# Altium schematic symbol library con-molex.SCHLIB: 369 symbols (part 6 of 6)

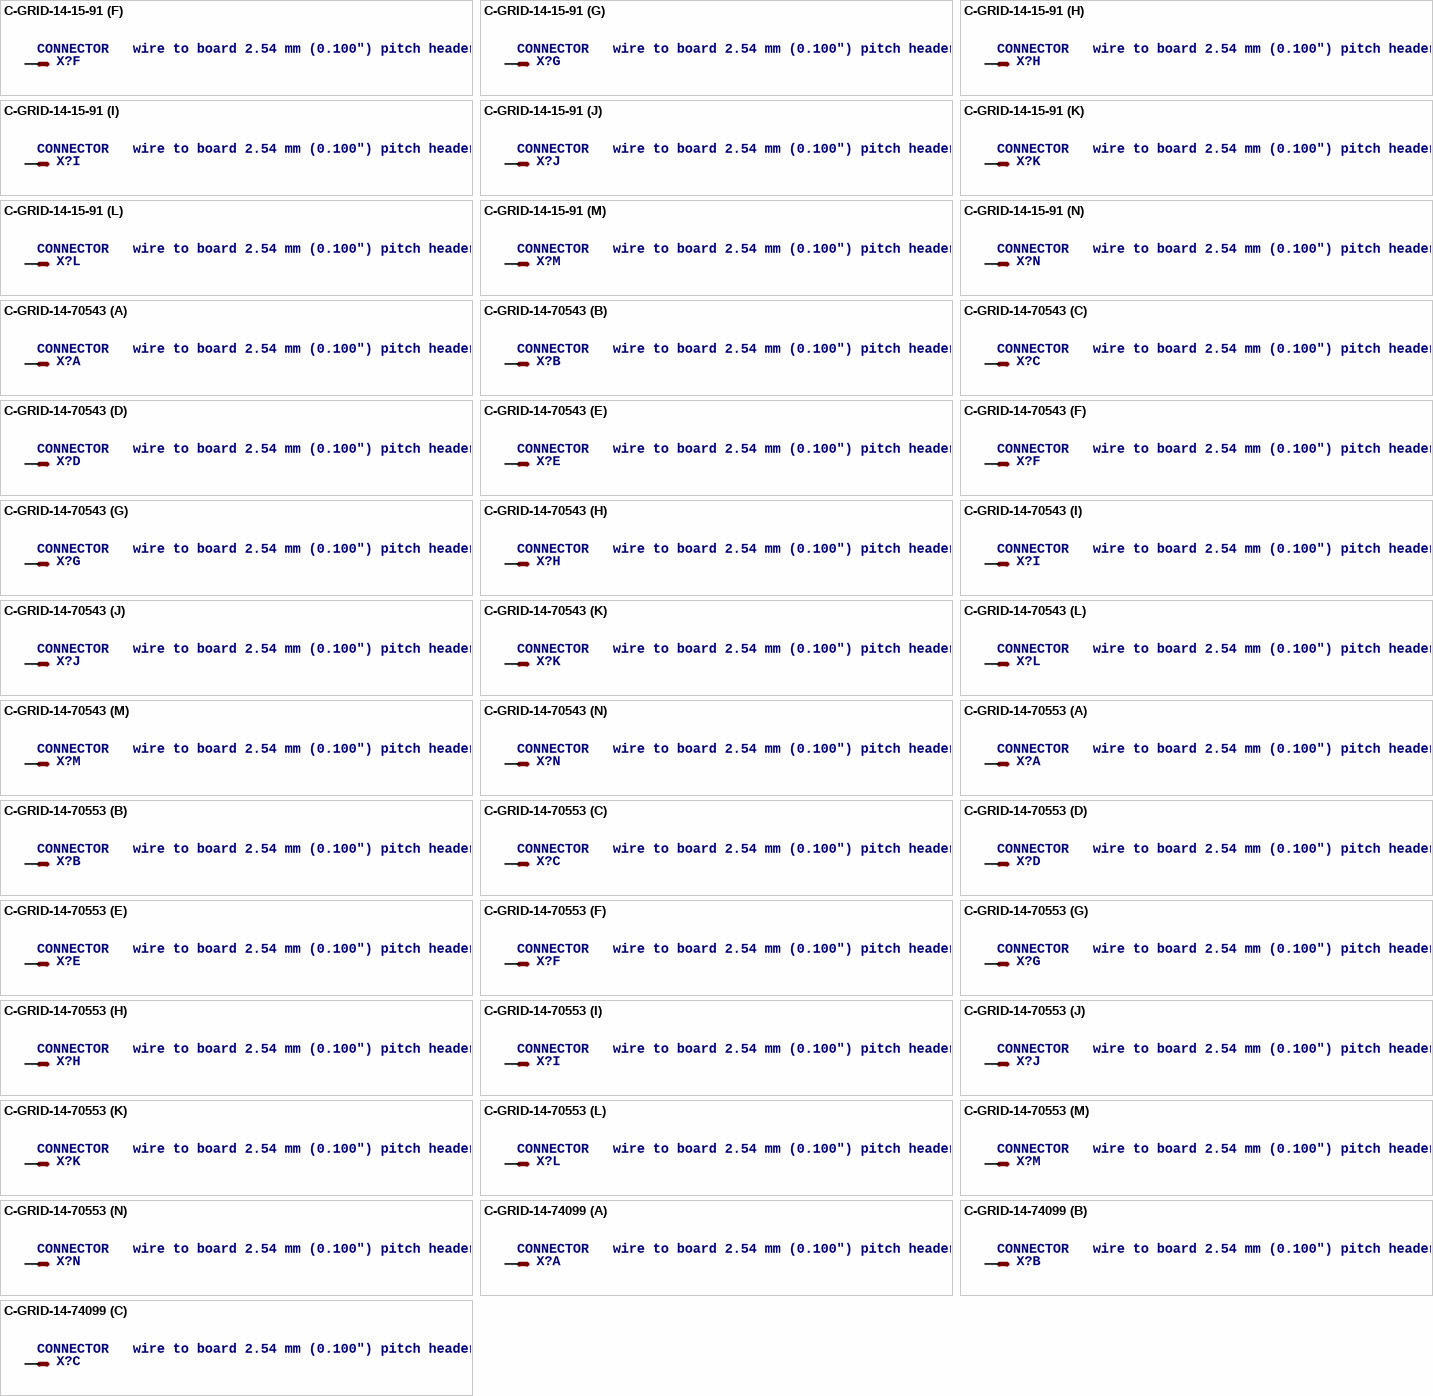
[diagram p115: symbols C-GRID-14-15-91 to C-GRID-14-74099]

## C-GRID-14-15-91
designator X?, comment CONNECTOR   wire to board 2.54 mm (0.100") pitch header
footprint 15-91-14
part A pins: 1 S
part B pins: 2 S
part C pins: 3 S
part D pins: 4 S
part E pins: 5 S
part F pins: 6 S
part G pins: 7 S
part H pins: 8 S
part I pins: 9 S
part J pins: 10 S
part K pins: 11 S
part L pins: 12 S
part M pins: 13 S
part N pins: 14 S

## C-GRID-14-70543
designator X?, comment CONNECTOR   wire to board 2.54 mm (0.100") pitch header
footprint 70543-14
part A pins: 1 S
part B pins: 2 S
part C pins: 3 S
part D pins: 4 S
part E pins: 5 S
part F pins: 6 S
part G pins: 7 S
part H pins: 8 S
part I pins: 9 S
part J pins: 10 S
part K pins: 11 S
part L pins: 12 S
part M pins: 13 S
part N pins: 14 S

## C-GRID-14-70553
designator X?, comment CONNECTOR   wire to board 2.54 mm (0.100") pitch header
footprint 70553-14
part A pins: 1 S
part B pins: 2 S
part C pins: 3 S
part D pins: 4 S
part E pins: 5 S
part F pins: 6 S
part G pins: 7 S
part H pins: 8 S
part I pins: 9 S
part J pins: 10 S
part K pins: 11 S
part L pins: 12 S
part M pins: 13 S
part N pins: 14 S

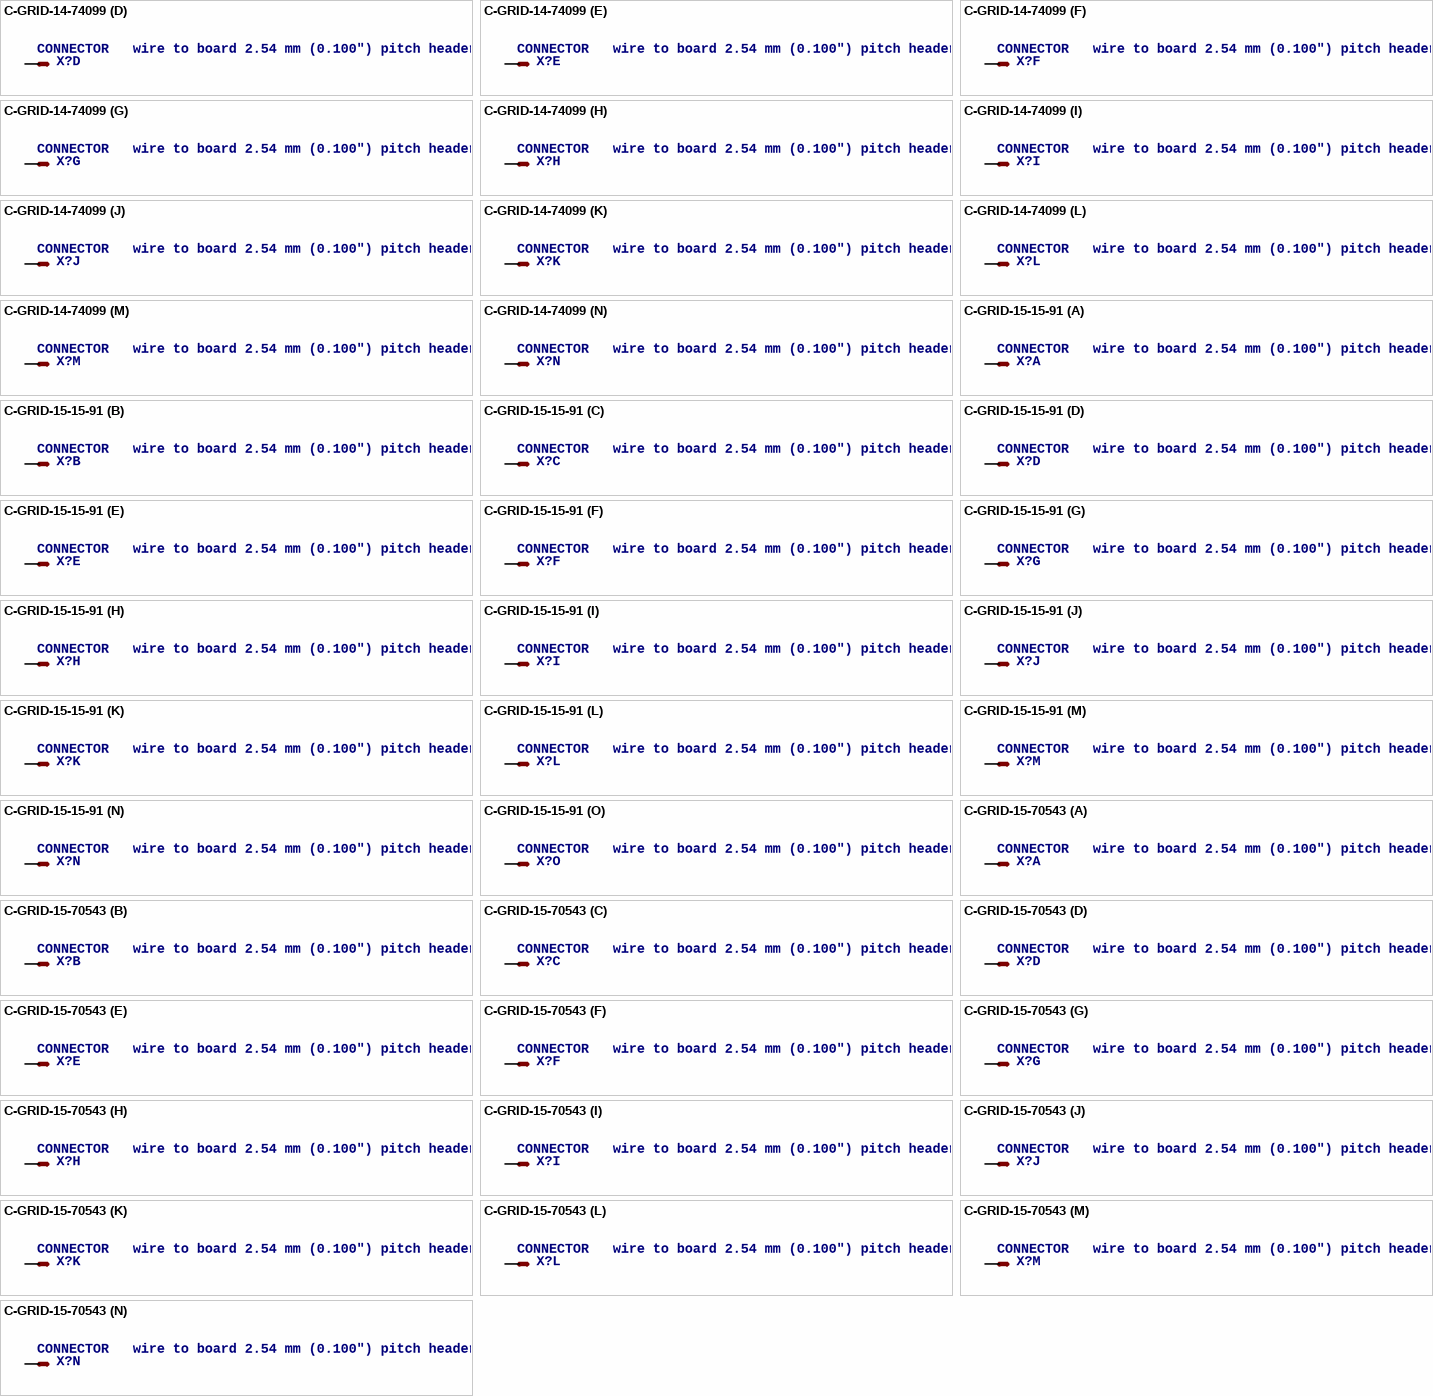
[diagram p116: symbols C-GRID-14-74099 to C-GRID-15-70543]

## C-GRID-14-74099
designator X?, comment CONNECTOR   wire to board 2.54 mm (0.100") pitch header
footprint 74099-14
part A pins: 1 S
part B pins: 2 S
part C pins: 3 S
part D pins: 4 S
part E pins: 5 S
part F pins: 6 S
part G pins: 7 S
part H pins: 8 S
part I pins: 9 S
part J pins: 10 S
part K pins: 11 S
part L pins: 12 S
part M pins: 13 S
part N pins: 14 S

## C-GRID-15-15-91
designator X?, comment CONNECTOR   wire to board 2.54 mm (0.100") pitch header
footprint 15-91-15
part A pins: 1 S
part B pins: 2 S
part C pins: 3 S
part D pins: 4 S
part E pins: 5 S
part F pins: 6 S
part G pins: 7 S
part H pins: 8 S
part I pins: 9 S
part J pins: 10 S
part K pins: 11 S
part L pins: 12 S
part M pins: 13 S
part N pins: 14 S
part O pins: 15 S

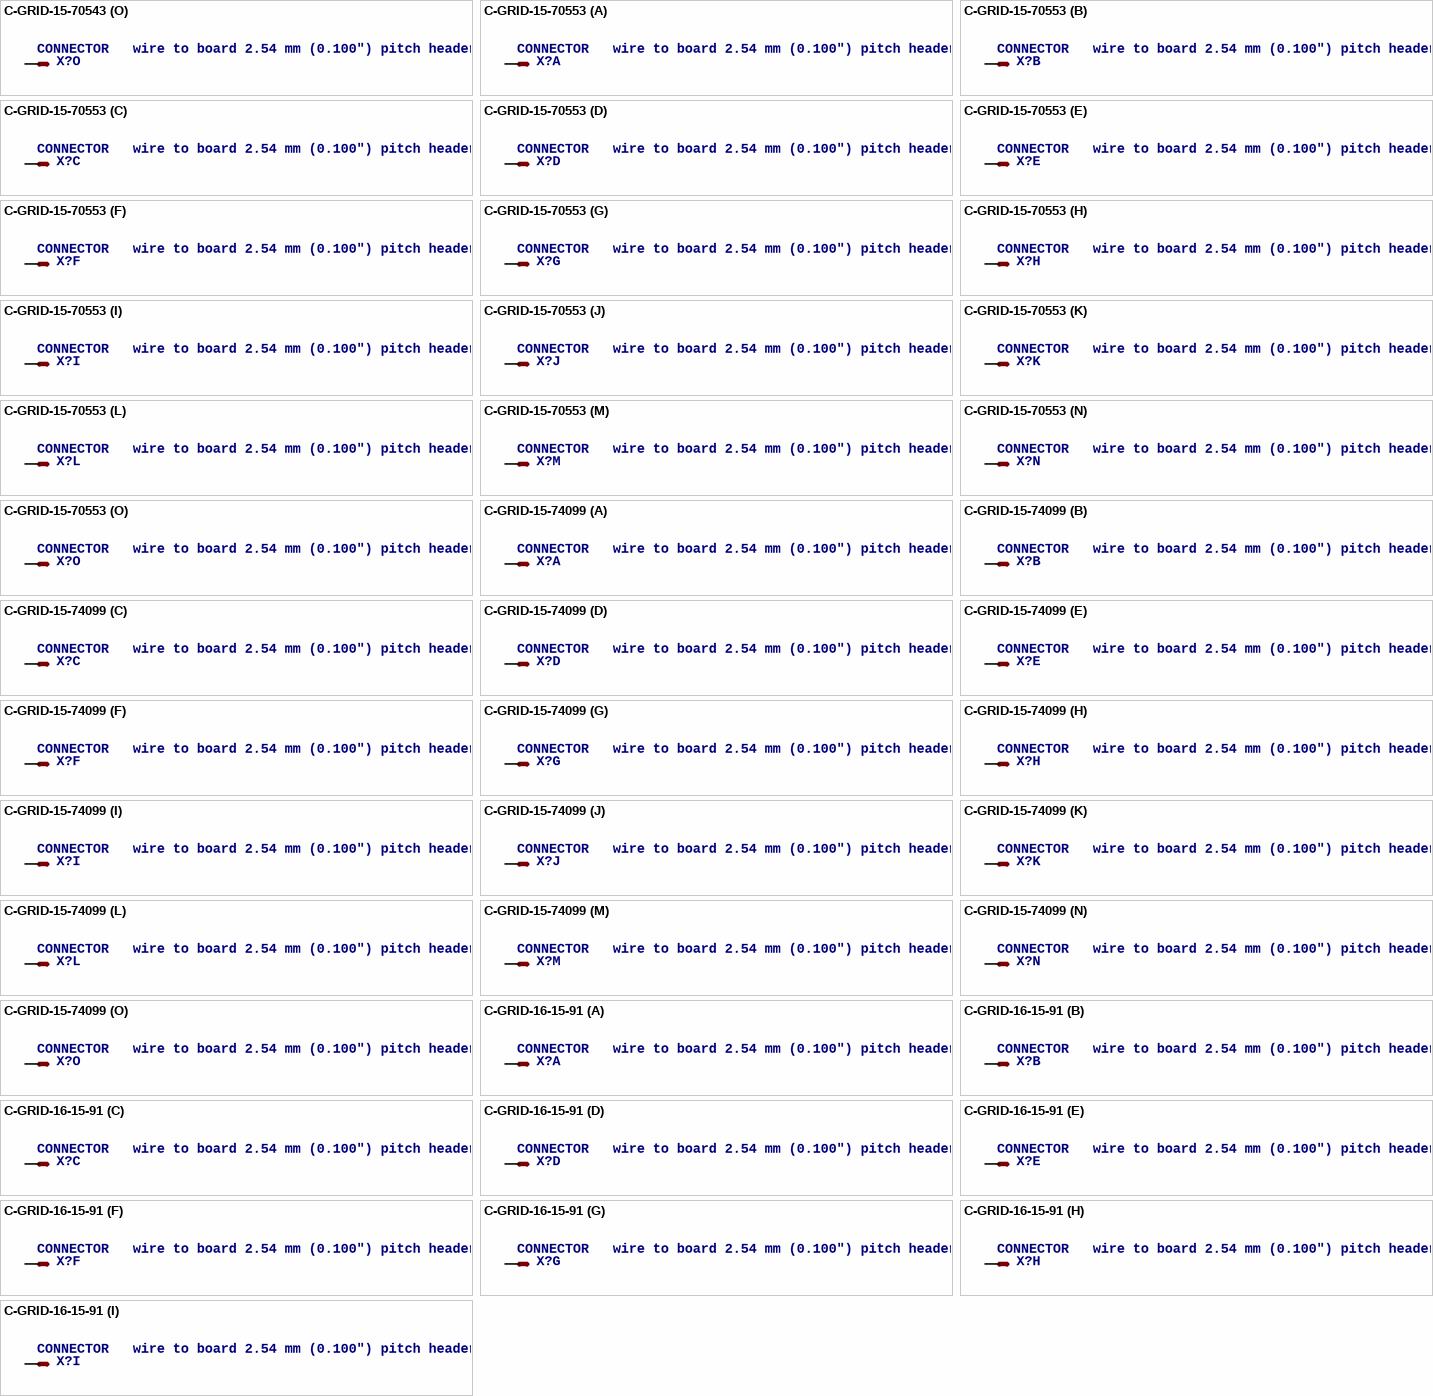
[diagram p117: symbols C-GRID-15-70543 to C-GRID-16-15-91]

## C-GRID-15-70543
designator X?, comment CONNECTOR   wire to board 2.54 mm (0.100") pitch header
footprint 70543-15
part A pins: 1 S
part B pins: 2 S
part C pins: 3 S
part D pins: 4 S
part E pins: 5 S
part F pins: 6 S
part G pins: 7 S
part H pins: 8 S
part I pins: 9 S
part J pins: 10 S
part K pins: 11 S
part L pins: 12 S
part M pins: 13 S
part N pins: 14 S
part O pins: 15 S

## C-GRID-15-70553
designator X?, comment CONNECTOR   wire to board 2.54 mm (0.100") pitch header
footprint 70553-15
part A pins: 1 S
part B pins: 2 S
part C pins: 3 S
part D pins: 4 S
part E pins: 5 S
part F pins: 6 S
part G pins: 7 S
part H pins: 8 S
part I pins: 9 S
part J pins: 10 S
part K pins: 11 S
part L pins: 12 S
part M pins: 13 S
part N pins: 14 S
part O pins: 15 S

## C-GRID-15-74099
designator X?, comment CONNECTOR   wire to board 2.54 mm (0.100") pitch header
footprint 74099-15
part A pins: 1 S
part B pins: 2 S
part C pins: 3 S
part D pins: 4 S
part E pins: 5 S
part F pins: 6 S
part G pins: 7 S
part H pins: 8 S
part I pins: 9 S
part J pins: 10 S
part K pins: 11 S
part L pins: 12 S
part M pins: 13 S
part N pins: 14 S
part O pins: 15 S

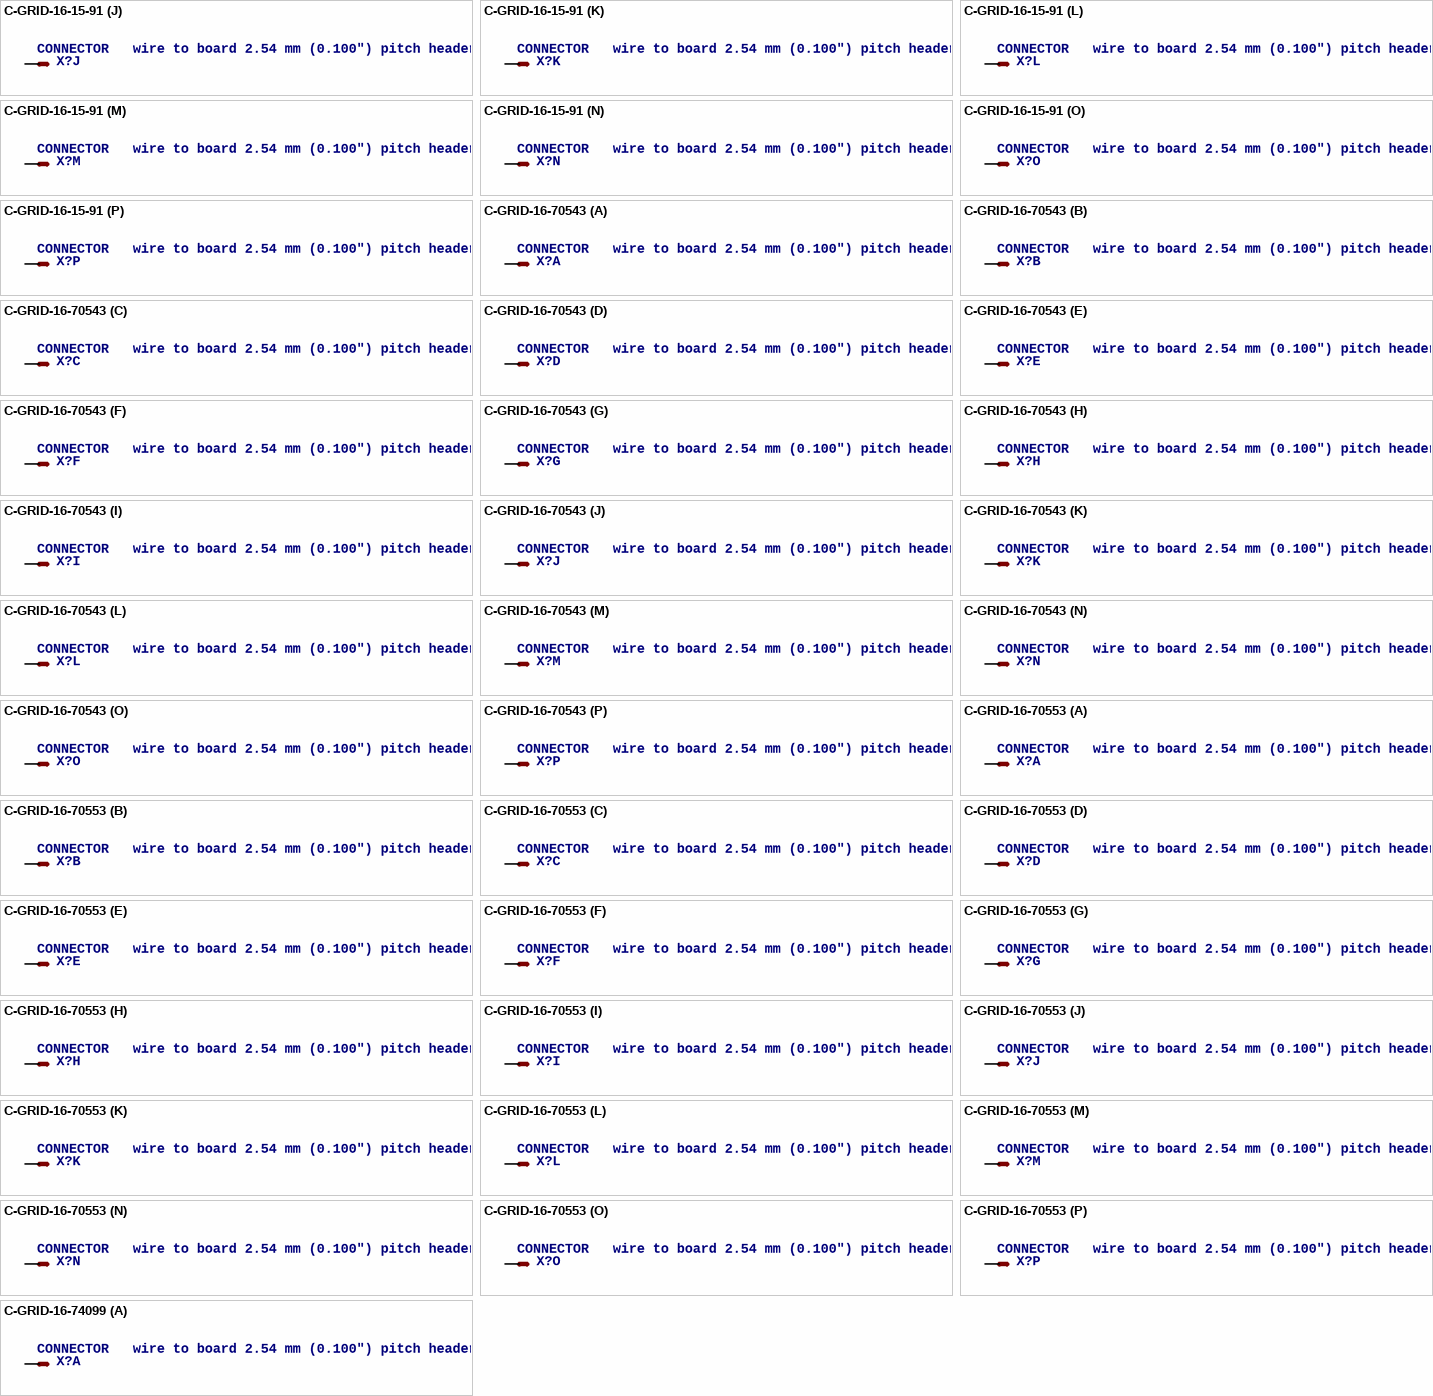
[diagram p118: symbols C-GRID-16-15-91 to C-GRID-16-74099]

## C-GRID-16-15-91
designator X?, comment CONNECTOR   wire to board 2.54 mm (0.100") pitch header
footprint 15-91-16
part A pins: 1 S
part B pins: 2 S
part C pins: 3 S
part D pins: 4 S
part E pins: 5 S
part F pins: 6 S
part G pins: 7 S
part H pins: 8 S
part I pins: 9 S
part J pins: 10 S
part K pins: 11 S
part L pins: 12 S
part M pins: 13 S
part N pins: 14 S
part O pins: 15 S
part P pins: 16 S

## C-GRID-16-70543
designator X?, comment CONNECTOR   wire to board 2.54 mm (0.100") pitch header
footprint 70543-16
part A pins: 1 S
part B pins: 2 S
part C pins: 3 S
part D pins: 4 S
part E pins: 5 S
part F pins: 6 S
part G pins: 7 S
part H pins: 8 S
part I pins: 9 S
part J pins: 10 S
part K pins: 11 S
part L pins: 12 S
part M pins: 13 S
part N pins: 14 S
part O pins: 15 S
part P pins: 16 S

## C-GRID-16-70553
designator X?, comment CONNECTOR   wire to board 2.54 mm (0.100") pitch header
footprint 70553-16
part A pins: 1 S
part B pins: 2 S
part C pins: 3 S
part D pins: 4 S
part E pins: 5 S
part F pins: 6 S
part G pins: 7 S
part H pins: 8 S
part I pins: 9 S
part J pins: 10 S
part K pins: 11 S
part L pins: 12 S
part M pins: 13 S
part N pins: 14 S
part O pins: 15 S
part P pins: 16 S

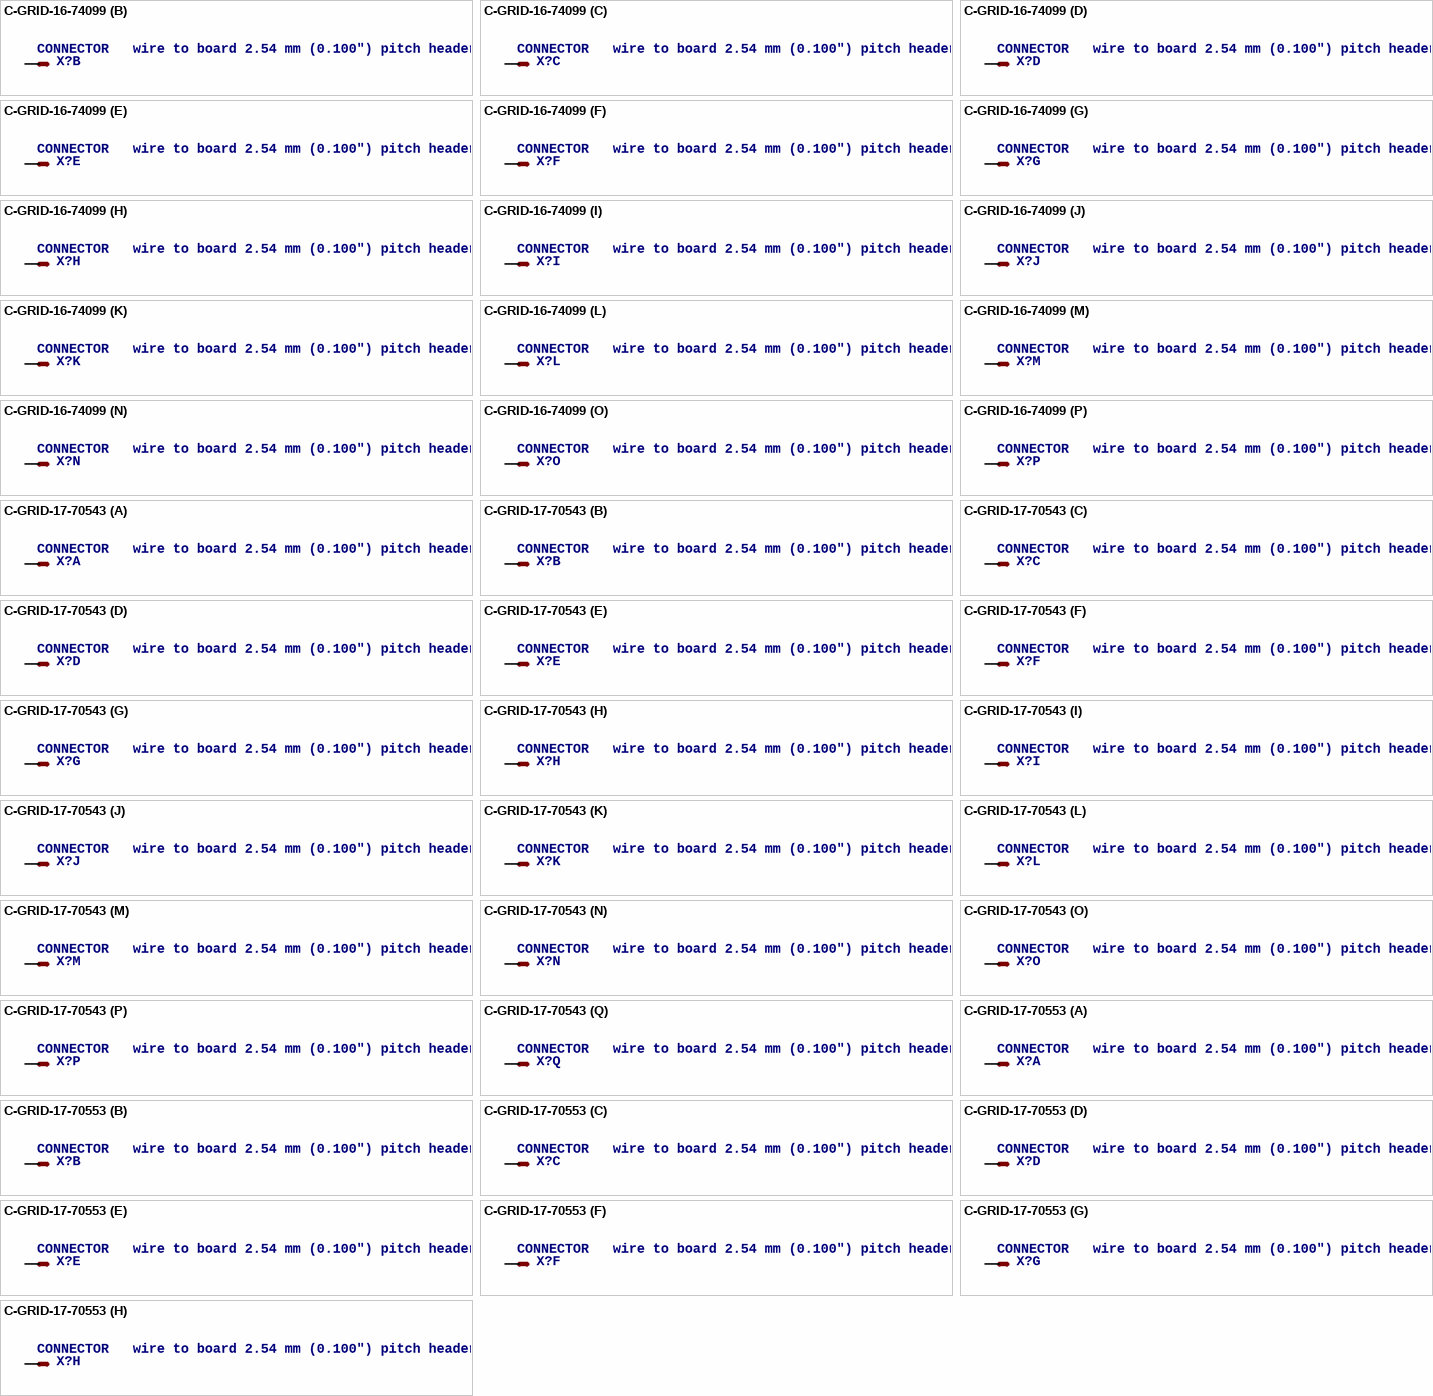
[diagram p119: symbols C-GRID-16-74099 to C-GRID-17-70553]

## C-GRID-16-74099
designator X?, comment CONNECTOR   wire to board 2.54 mm (0.100") pitch header
footprint 74099-16
part A pins: 1 S
part B pins: 2 S
part C pins: 3 S
part D pins: 4 S
part E pins: 5 S
part F pins: 6 S
part G pins: 7 S
part H pins: 8 S
part I pins: 9 S
part J pins: 10 S
part K pins: 11 S
part L pins: 12 S
part M pins: 13 S
part N pins: 14 S
part O pins: 15 S
part P pins: 16 S

## C-GRID-17-70543
designator X?, comment CONNECTOR   wire to board 2.54 mm (0.100") pitch header
footprint 70543-17
part A pins: 1 S
part B pins: 2 S
part C pins: 3 S
part D pins: 4 S
part E pins: 5 S
part F pins: 6 S
part G pins: 7 S
part H pins: 8 S
part I pins: 9 S
part J pins: 10 S
part K pins: 11 S
part L pins: 12 S
part M pins: 13 S
part N pins: 14 S
part O pins: 15 S
part P pins: 16 S
part Q pins: 17 S

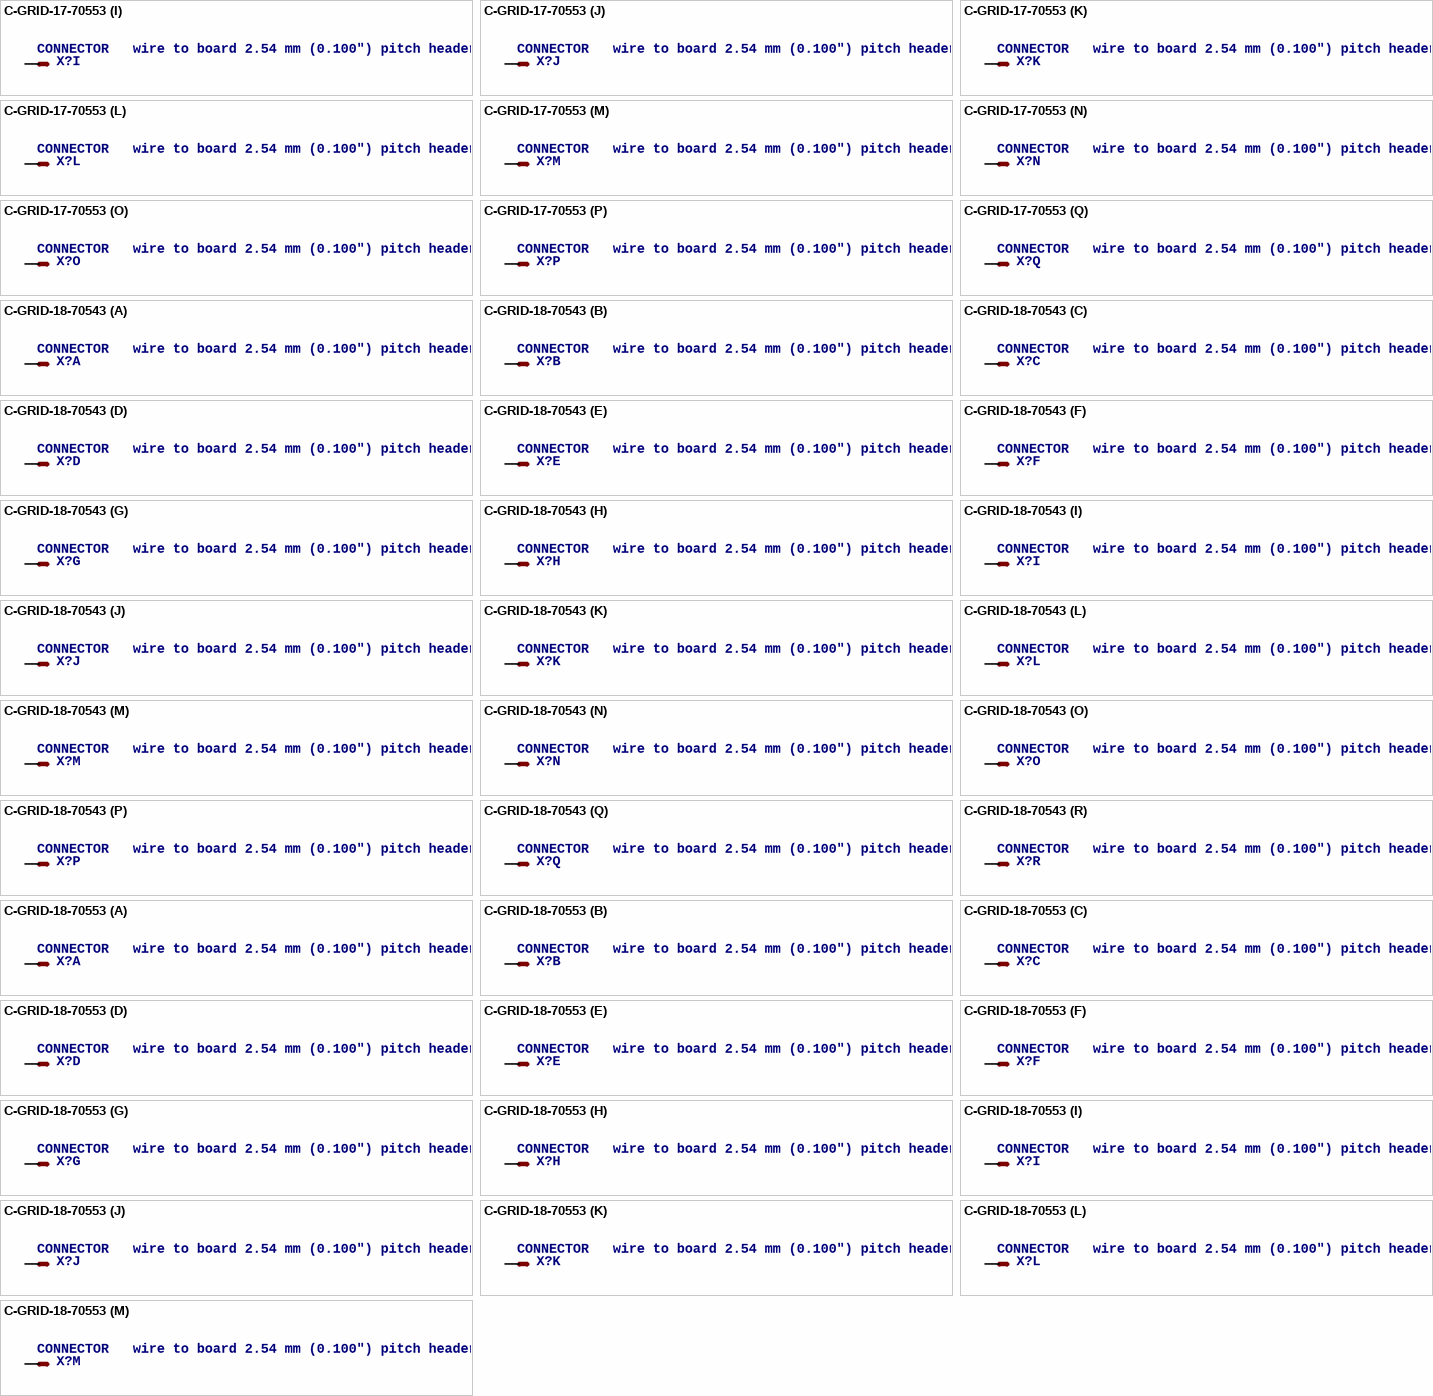
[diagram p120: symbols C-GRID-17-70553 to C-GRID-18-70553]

## C-GRID-17-70553
designator X?, comment CONNECTOR   wire to board 2.54 mm (0.100") pitch header
footprint 70553-17
part A pins: 1 S
part B pins: 2 S
part C pins: 3 S
part D pins: 4 S
part E pins: 5 S
part F pins: 6 S
part G pins: 7 S
part H pins: 8 S
part I pins: 9 S
part J pins: 10 S
part K pins: 11 S
part L pins: 12 S
part M pins: 13 S
part N pins: 14 S
part O pins: 15 S
part P pins: 16 S
part Q pins: 17 S

## C-GRID-18-70543
designator X?, comment CONNECTOR   wire to board 2.54 mm (0.100") pitch header
footprint 70543-18
part A pins: 1 S
part B pins: 2 S
part C pins: 3 S
part D pins: 4 S
part E pins: 5 S
part F pins: 6 S
part G pins: 7 S
part H pins: 8 S
part I pins: 9 S
part J pins: 10 S
part K pins: 11 S
part L pins: 12 S
part M pins: 13 S
part N pins: 14 S
part O pins: 15 S
part P pins: 16 S
part Q pins: 17 S
part R pins: 18 S

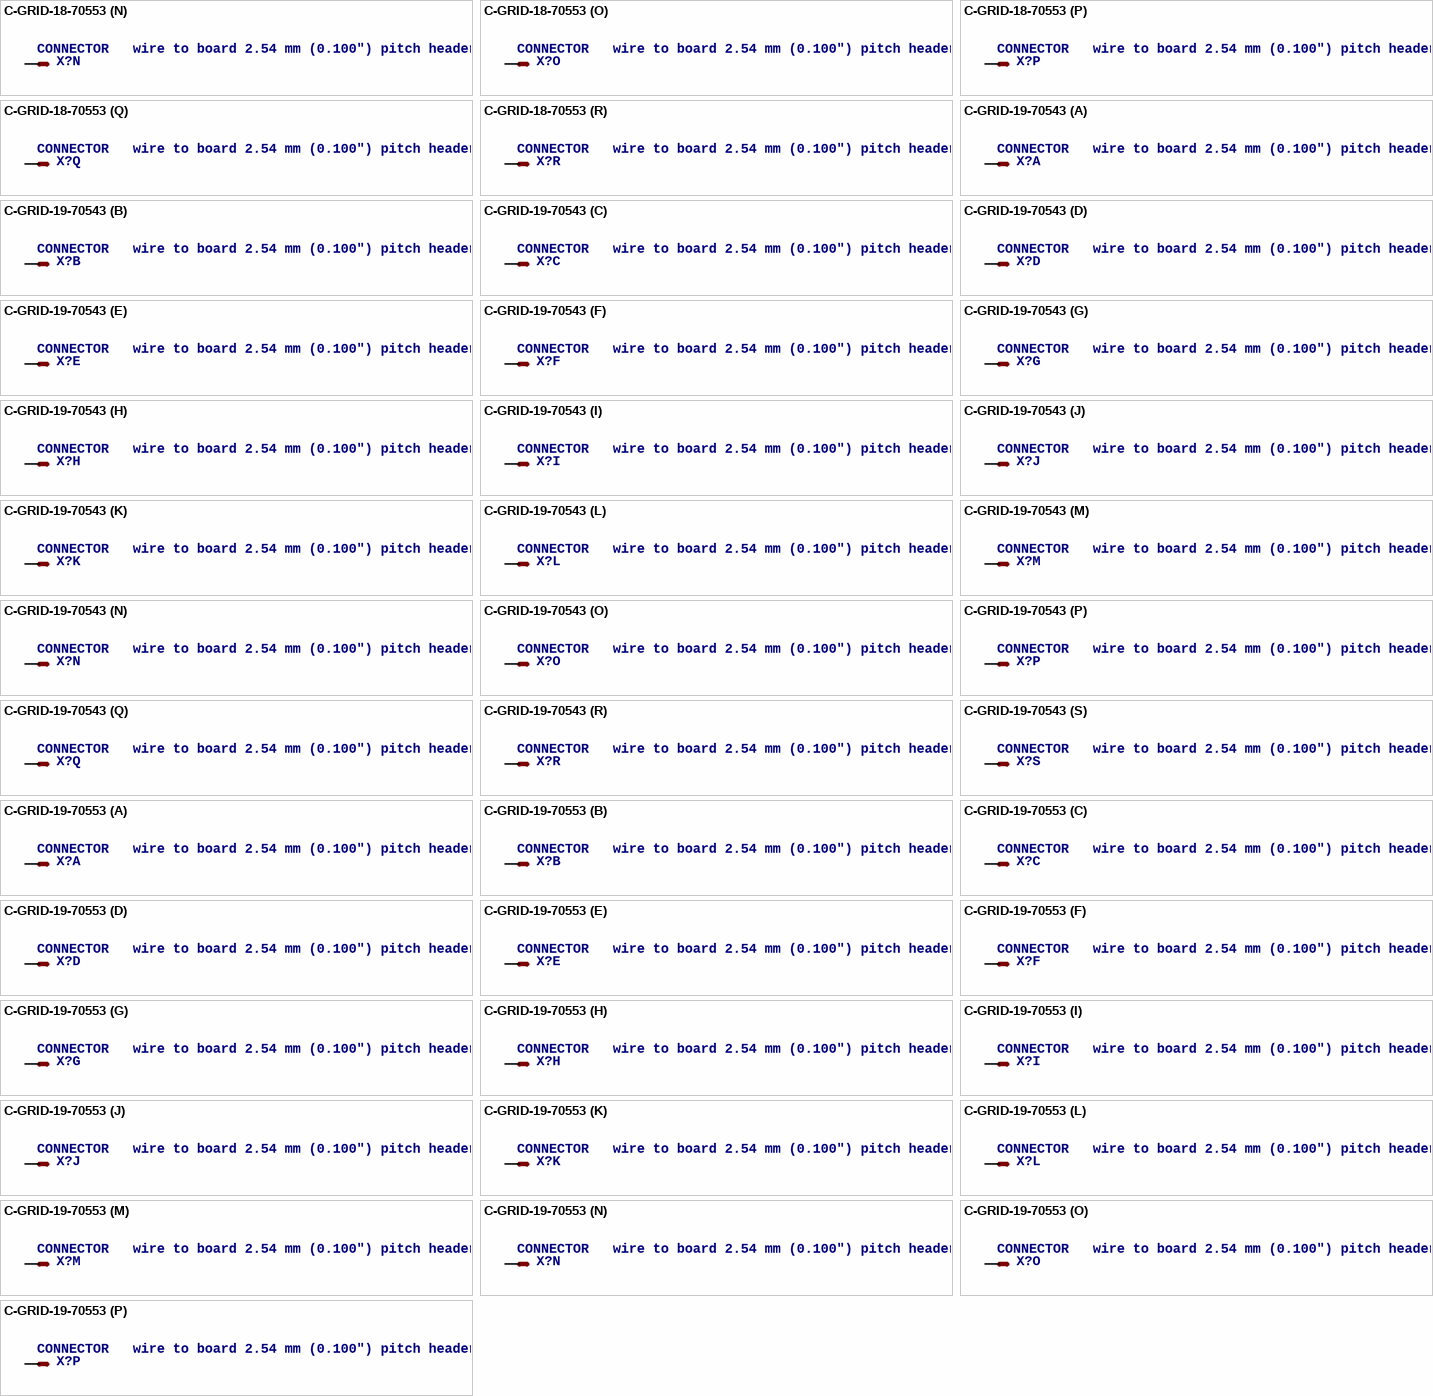
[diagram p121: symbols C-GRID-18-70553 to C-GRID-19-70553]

## C-GRID-18-70553
designator X?, comment CONNECTOR   wire to board 2.54 mm (0.100") pitch header
footprint 70553-18
part A pins: 1 S
part B pins: 2 S
part C pins: 3 S
part D pins: 4 S
part E pins: 5 S
part F pins: 6 S
part G pins: 7 S
part H pins: 8 S
part I pins: 9 S
part J pins: 10 S
part K pins: 11 S
part L pins: 12 S
part M pins: 13 S
part N pins: 14 S
part O pins: 15 S
part P pins: 16 S
part Q pins: 17 S
part R pins: 18 S

## C-GRID-19-70543
designator X?, comment CONNECTOR   wire to board 2.54 mm (0.100") pitch header
footprint 70543-19
part A pins: 1 S
part B pins: 2 S
part C pins: 3 S
part D pins: 4 S
part E pins: 5 S
part F pins: 6 S
part G pins: 7 S
part H pins: 8 S
part I pins: 9 S
part J pins: 10 S
part K pins: 11 S
part L pins: 12 S
part M pins: 13 S
part N pins: 14 S
part O pins: 15 S
part P pins: 16 S
part Q pins: 17 S
part R pins: 18 S
part S pins: 19 S

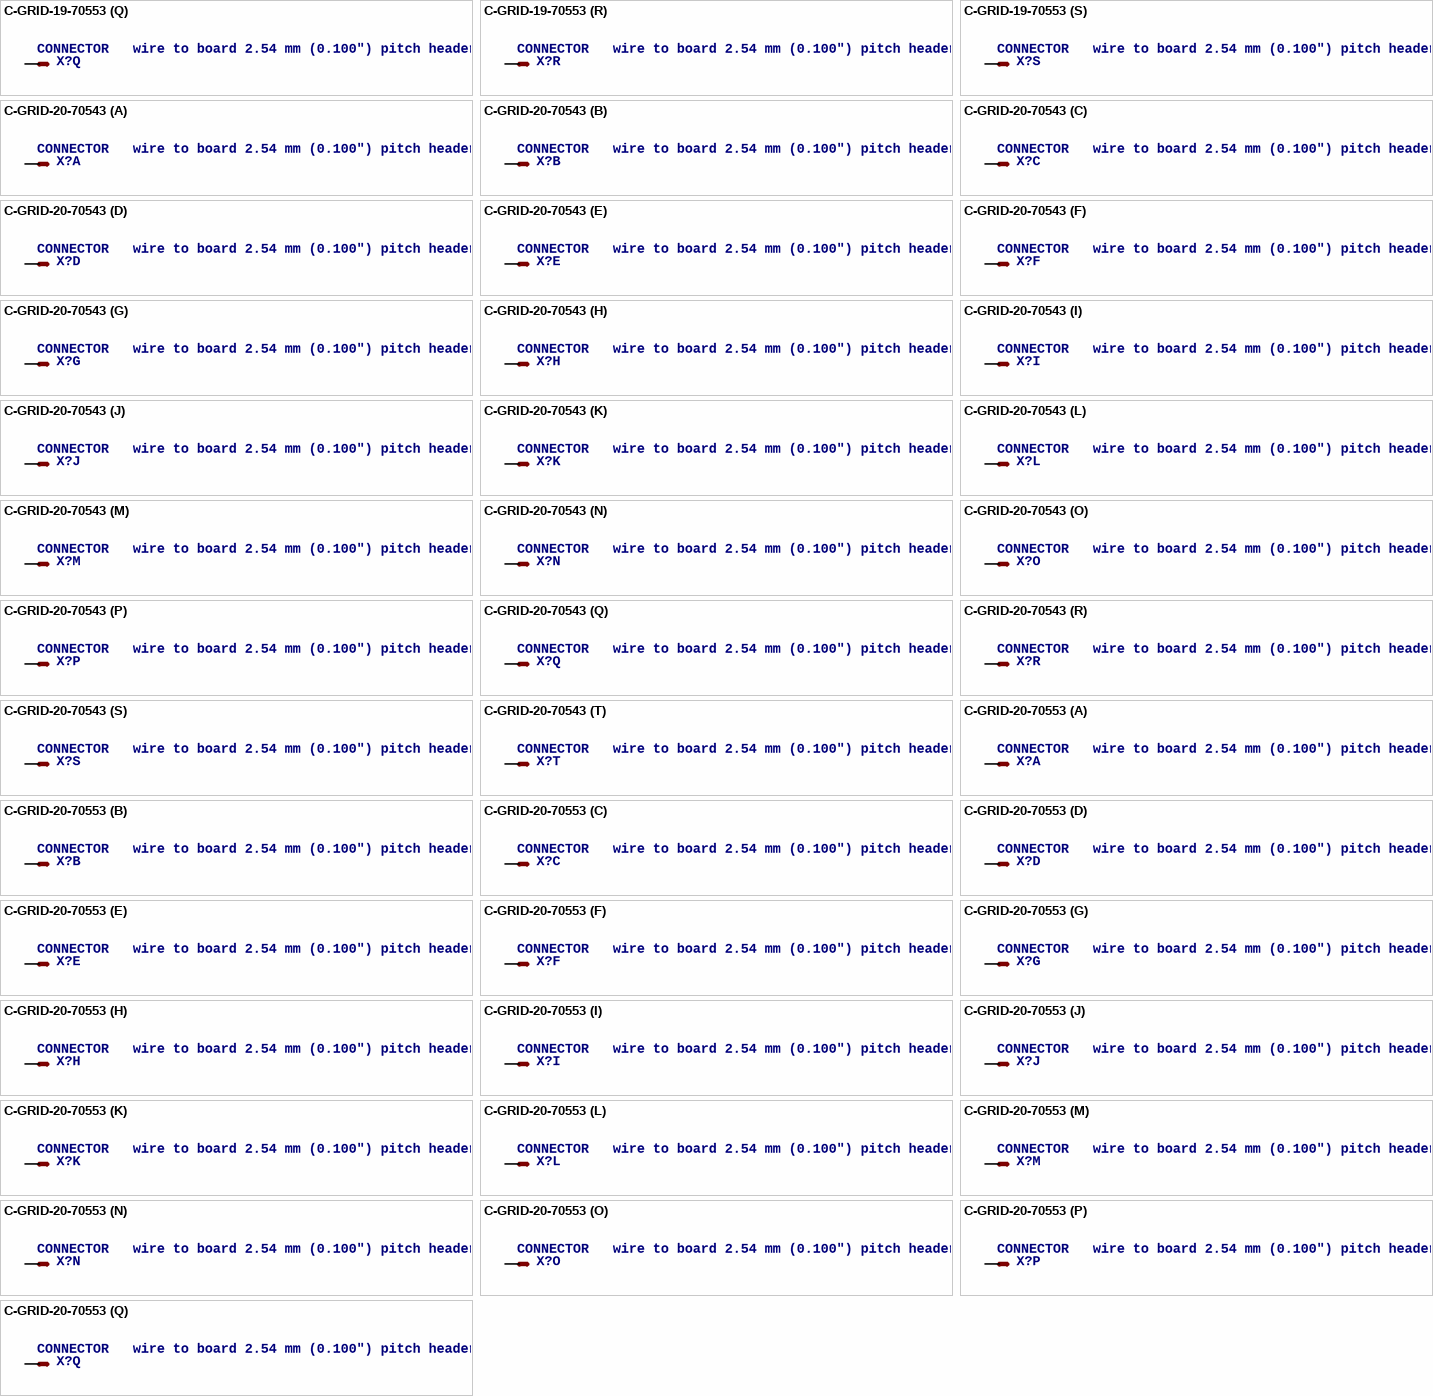
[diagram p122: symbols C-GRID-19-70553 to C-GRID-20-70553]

## C-GRID-19-70553
designator X?, comment CONNECTOR   wire to board 2.54 mm (0.100") pitch header
footprint 70553-19
part A pins: 1 S
part B pins: 2 S
part C pins: 3 S
part D pins: 4 S
part E pins: 5 S
part F pins: 6 S
part G pins: 7 S
part H pins: 8 S
part I pins: 9 S
part J pins: 10 S
part K pins: 11 S
part L pins: 12 S
part M pins: 13 S
part N pins: 14 S
part O pins: 15 S
part P pins: 16 S
part Q pins: 17 S
part R pins: 18 S
part S pins: 19 S

## C-GRID-20-70543
designator X?, comment CONNECTOR   wire to board 2.54 mm (0.100") pitch header
footprint 70543-20
part A pins: 1 S
part B pins: 2 S
part C pins: 3 S
part D pins: 4 S
part E pins: 5 S
part F pins: 6 S
part G pins: 7 S
part H pins: 8 S
part I pins: 9 S
part J pins: 10 S
part K pins: 11 S
part L pins: 12 S
part M pins: 13 S
part N pins: 14 S
part O pins: 15 S
part P pins: 16 S
part Q pins: 17 S
part R pins: 18 S
part S pins: 19 S
part T pins: 20 S

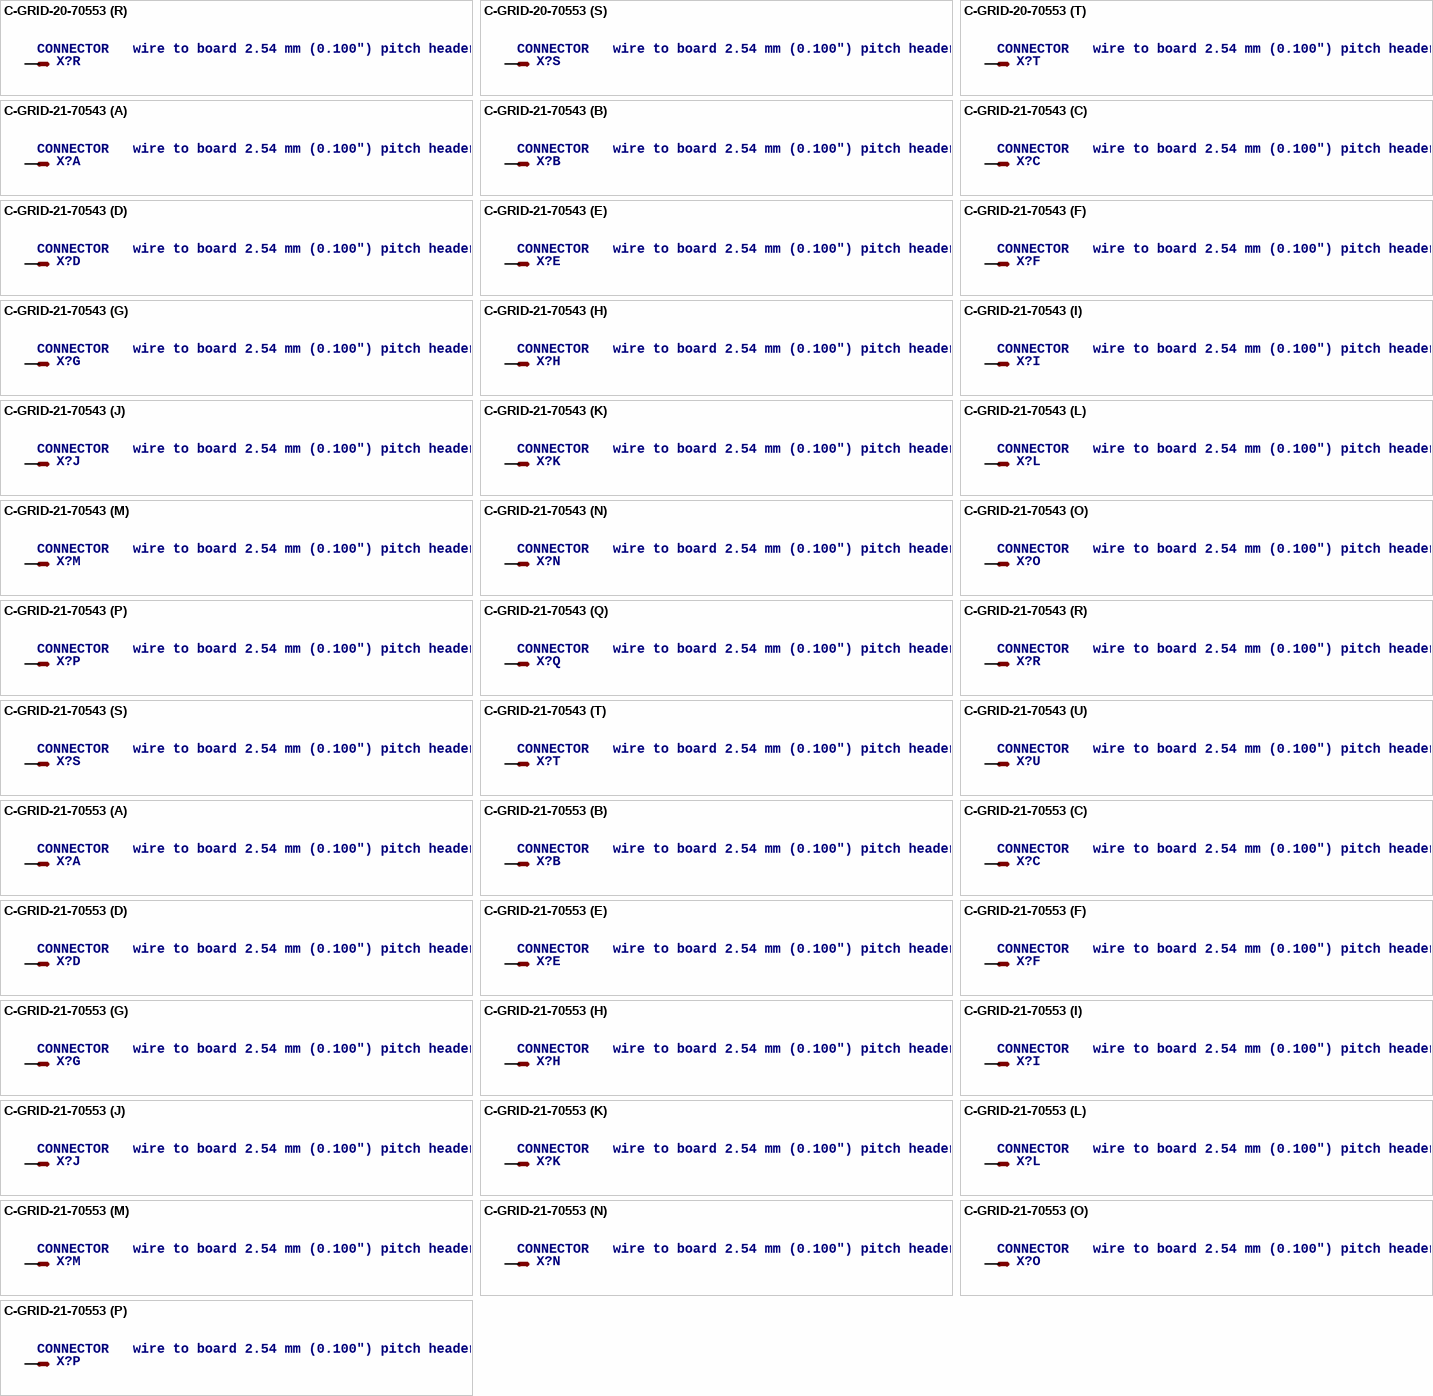
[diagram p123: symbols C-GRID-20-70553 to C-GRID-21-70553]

## C-GRID-20-70553
designator X?, comment CONNECTOR   wire to board 2.54 mm (0.100") pitch header
footprint 70553-20
part A pins: 1 S
part B pins: 2 S
part C pins: 3 S
part D pins: 4 S
part E pins: 5 S
part F pins: 6 S
part G pins: 7 S
part H pins: 8 S
part I pins: 9 S
part J pins: 10 S
part K pins: 11 S
part L pins: 12 S
part M pins: 13 S
part N pins: 14 S
part O pins: 15 S
part P pins: 16 S
part Q pins: 17 S
part R pins: 18 S
part S pins: 19 S
part T pins: 20 S

## C-GRID-21-70543
designator X?, comment CONNECTOR   wire to board 2.54 mm (0.100") pitch header
footprint 70543-21
part A pins: 1 S
part B pins: 2 S
part C pins: 3 S
part D pins: 4 S
part E pins: 5 S
part F pins: 6 S
part G pins: 7 S
part H pins: 8 S
part I pins: 9 S
part J pins: 10 S
part K pins: 11 S
part L pins: 12 S
part M pins: 13 S
part N pins: 14 S
part O pins: 15 S
part P pins: 16 S
part Q pins: 17 S
part R pins: 18 S
part S pins: 19 S
part T pins: 20 S
part U pins: 21 S

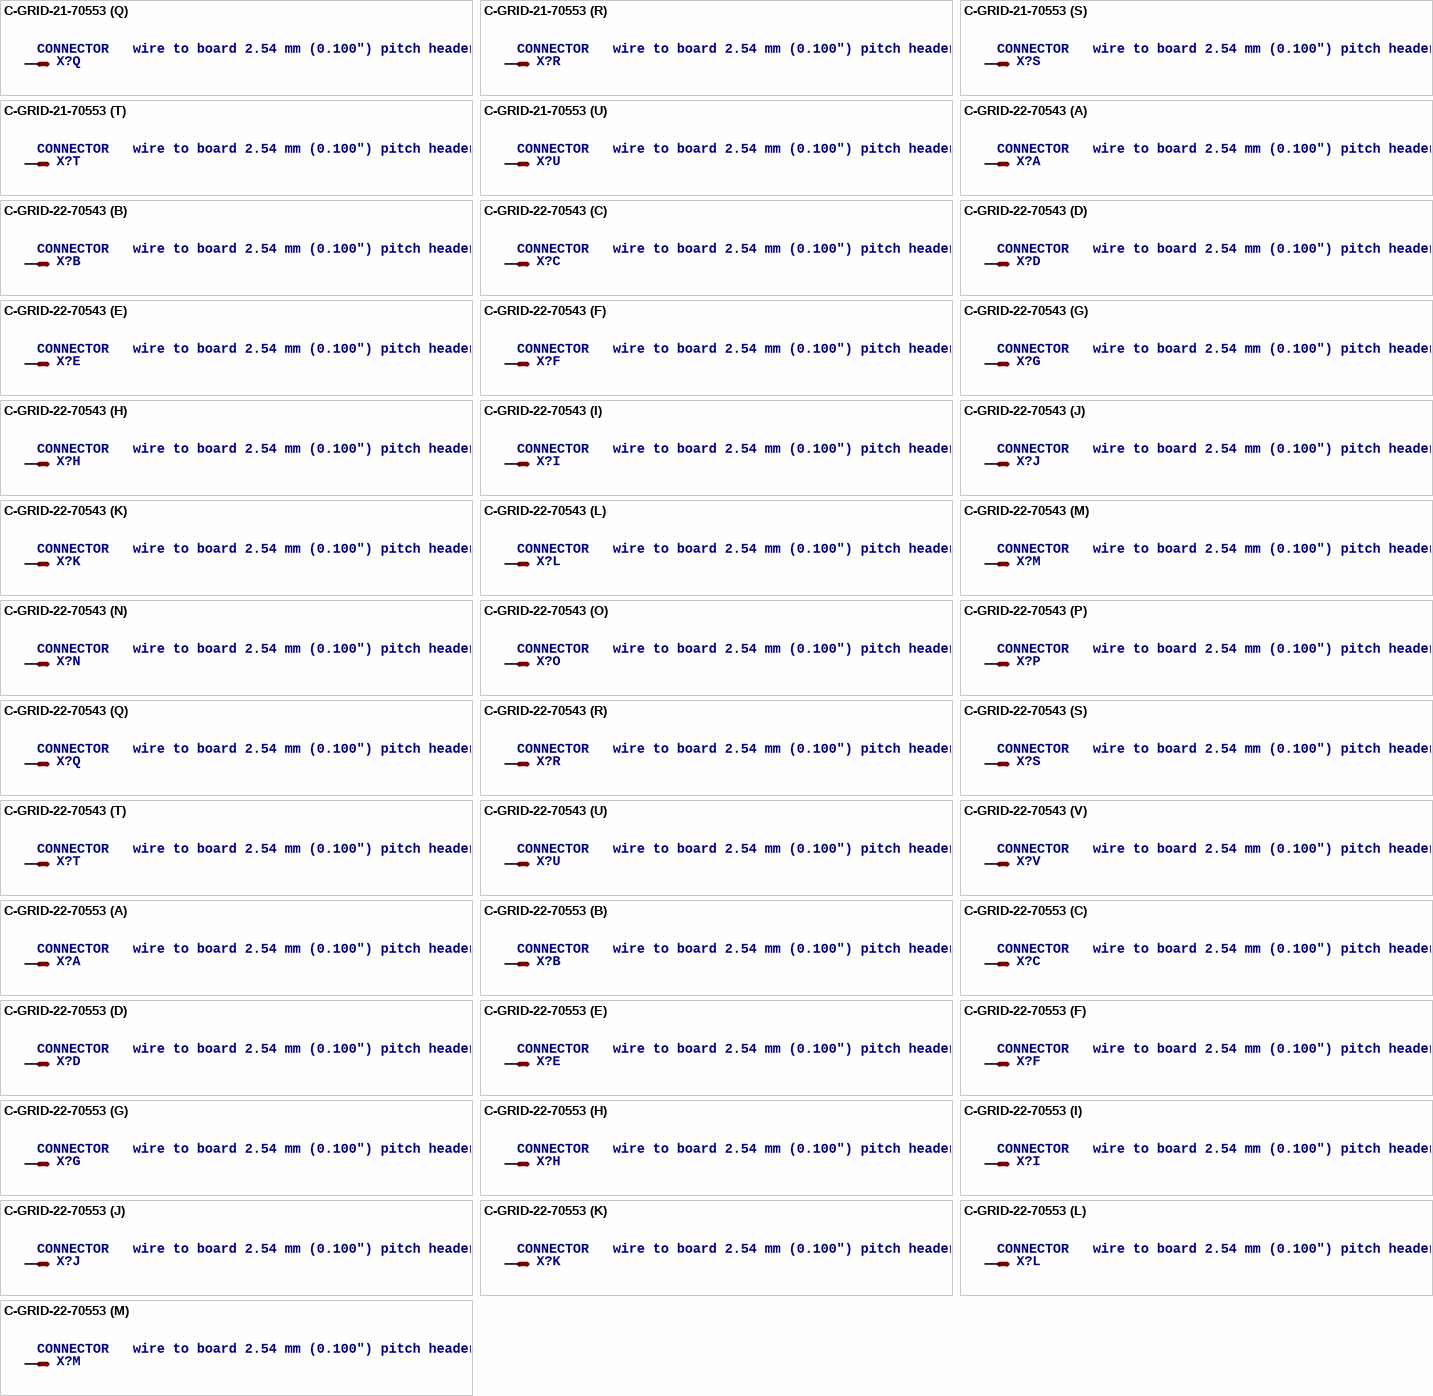
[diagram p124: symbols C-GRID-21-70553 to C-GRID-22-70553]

## C-GRID-21-70553
designator X?, comment CONNECTOR   wire to board 2.54 mm (0.100") pitch header
footprint 70553-21
part A pins: 1 S
part B pins: 2 S
part C pins: 3 S
part D pins: 4 S
part E pins: 5 S
part F pins: 6 S
part G pins: 7 S
part H pins: 8 S
part I pins: 9 S
part J pins: 10 S
part K pins: 11 S
part L pins: 12 S
part M pins: 13 S
part N pins: 14 S
part O pins: 15 S
part P pins: 16 S
part Q pins: 17 S
part R pins: 18 S
part S pins: 19 S
part T pins: 20 S
part U pins: 21 S

## C-GRID-22-70543
designator X?, comment CONNECTOR   wire to board 2.54 mm (0.100") pitch header
footprint 70543-22
part A pins: 1 S
part B pins: 2 S
part C pins: 3 S
part D pins: 4 S
part E pins: 5 S
part F pins: 6 S
part G pins: 7 S
part H pins: 8 S
part I pins: 9 S
part J pins: 10 S
part K pins: 11 S
part L pins: 12 S
part M pins: 13 S
part N pins: 14 S
part O pins: 15 S
part P pins: 16 S
part Q pins: 17 S
part R pins: 18 S
part S pins: 19 S
part T pins: 20 S
part U pins: 21 S
part V pins: 22 S

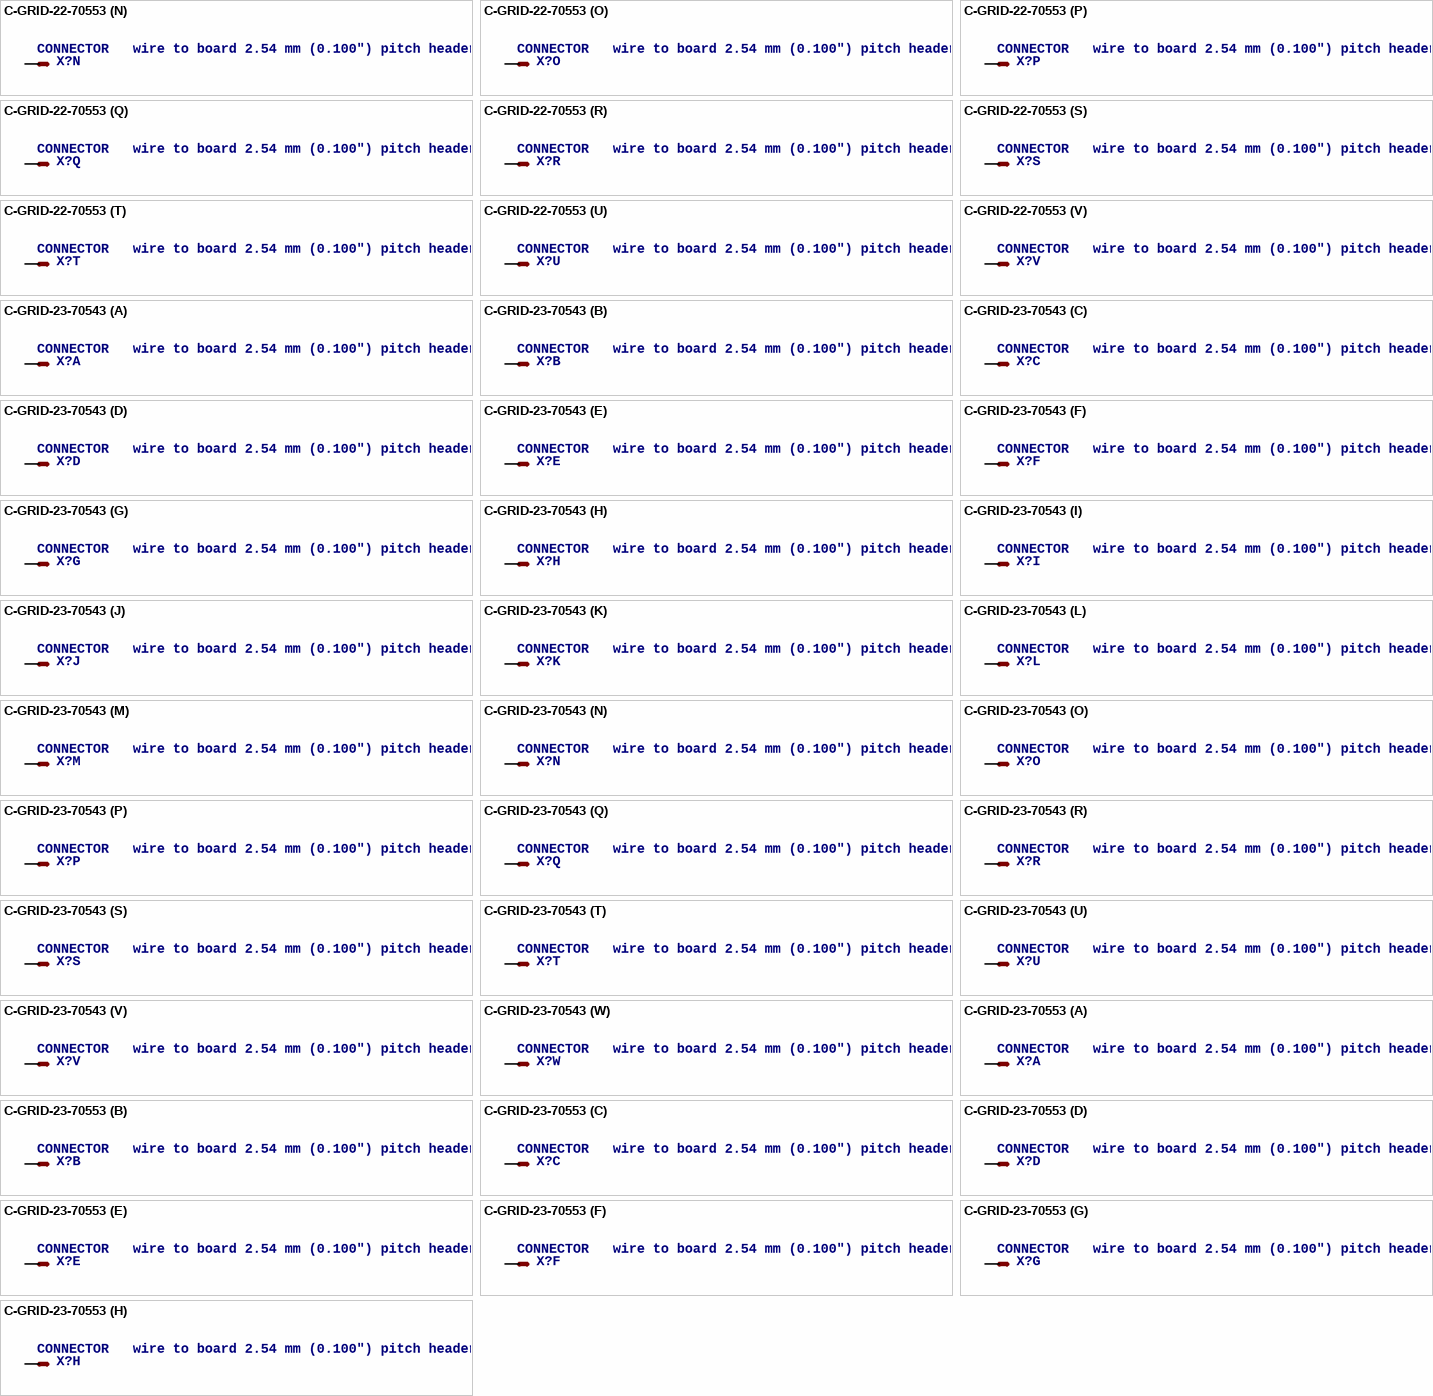
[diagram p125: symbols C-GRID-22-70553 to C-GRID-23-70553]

## C-GRID-22-70553
designator X?, comment CONNECTOR   wire to board 2.54 mm (0.100") pitch header
footprint 70553-22
part A pins: 1 S
part B pins: 2 S
part C pins: 3 S
part D pins: 4 S
part E pins: 5 S
part F pins: 6 S
part G pins: 7 S
part H pins: 8 S
part I pins: 9 S
part J pins: 10 S
part K pins: 11 S
part L pins: 12 S
part M pins: 13 S
part N pins: 14 S
part O pins: 15 S
part P pins: 16 S
part Q pins: 17 S
part R pins: 18 S
part S pins: 19 S
part T pins: 20 S
part U pins: 21 S
part V pins: 22 S

## C-GRID-23-70543
designator X?, comment CONNECTOR   wire to board 2.54 mm (0.100") pitch header
footprint 70543-23
part A pins: 1 S
part B pins: 2 S
part C pins: 3 S
part D pins: 4 S
part E pins: 5 S
part F pins: 6 S
part G pins: 7 S
part H pins: 8 S
part I pins: 9 S
part J pins: 10 S
part K pins: 11 S
part L pins: 12 S
part M pins: 13 S
part N pins: 14 S
part O pins: 15 S
part P pins: 16 S
part Q pins: 17 S
part R pins: 18 S
part S pins: 19 S
part T pins: 20 S
part U pins: 21 S
part V pins: 22 S
part W pins: 23 S

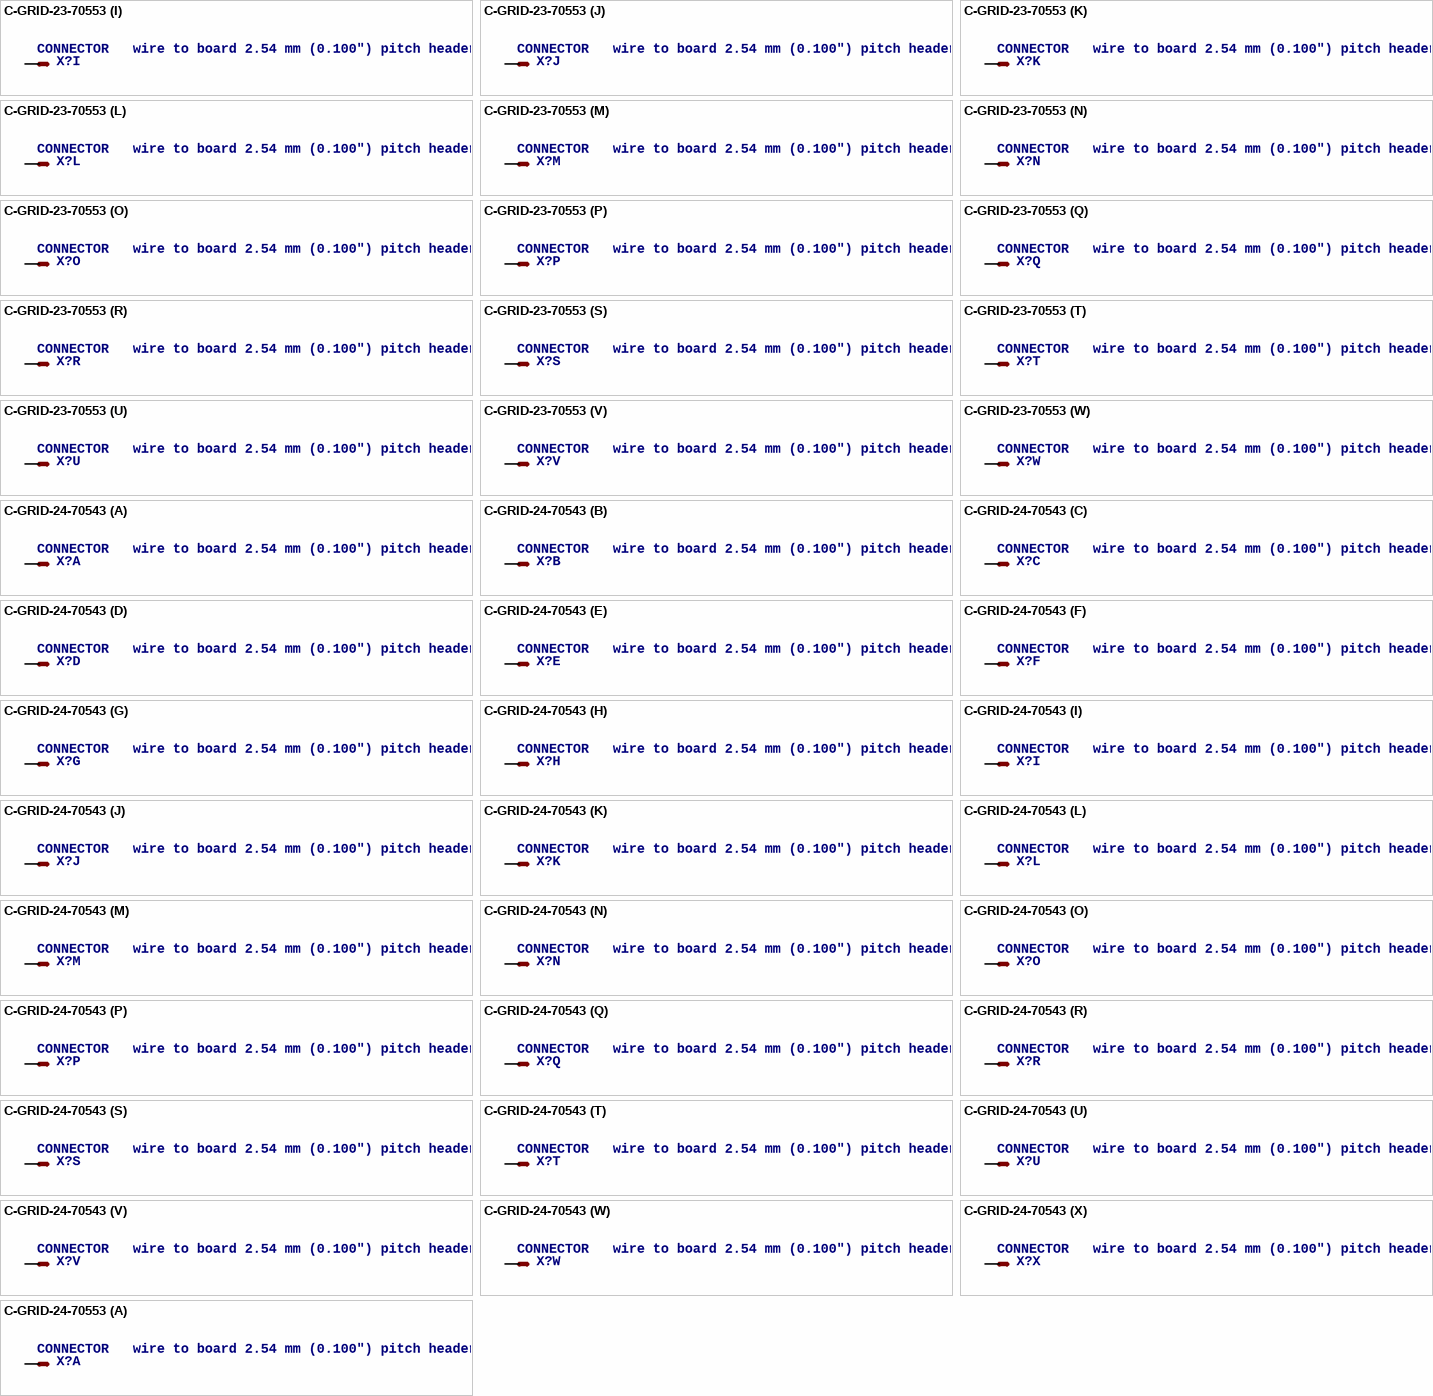
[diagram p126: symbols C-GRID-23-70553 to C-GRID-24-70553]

## C-GRID-23-70553
designator X?, comment CONNECTOR   wire to board 2.54 mm (0.100") pitch header
footprint 70553-23
part A pins: 1 S
part B pins: 2 S
part C pins: 3 S
part D pins: 4 S
part E pins: 5 S
part F pins: 6 S
part G pins: 7 S
part H pins: 8 S
part I pins: 9 S
part J pins: 10 S
part K pins: 11 S
part L pins: 12 S
part M pins: 13 S
part N pins: 14 S
part O pins: 15 S
part P pins: 16 S
part Q pins: 17 S
part R pins: 18 S
part S pins: 19 S
part T pins: 20 S
part U pins: 21 S
part V pins: 22 S
part W pins: 23 S

## C-GRID-24-70543
designator X?, comment CONNECTOR   wire to board 2.54 mm (0.100") pitch header
footprint 70543-24
part A pins: 1 S
part B pins: 2 S
part C pins: 3 S
part D pins: 4 S
part E pins: 5 S
part F pins: 6 S
part G pins: 7 S
part H pins: 8 S
part I pins: 9 S
part J pins: 10 S
part K pins: 11 S
part L pins: 12 S
part M pins: 13 S
part N pins: 14 S
part O pins: 15 S
part P pins: 16 S
part Q pins: 17 S
part R pins: 18 S
part S pins: 19 S
part T pins: 20 S
part U pins: 21 S
part V pins: 22 S
part W pins: 23 S
part X pins: 24 S

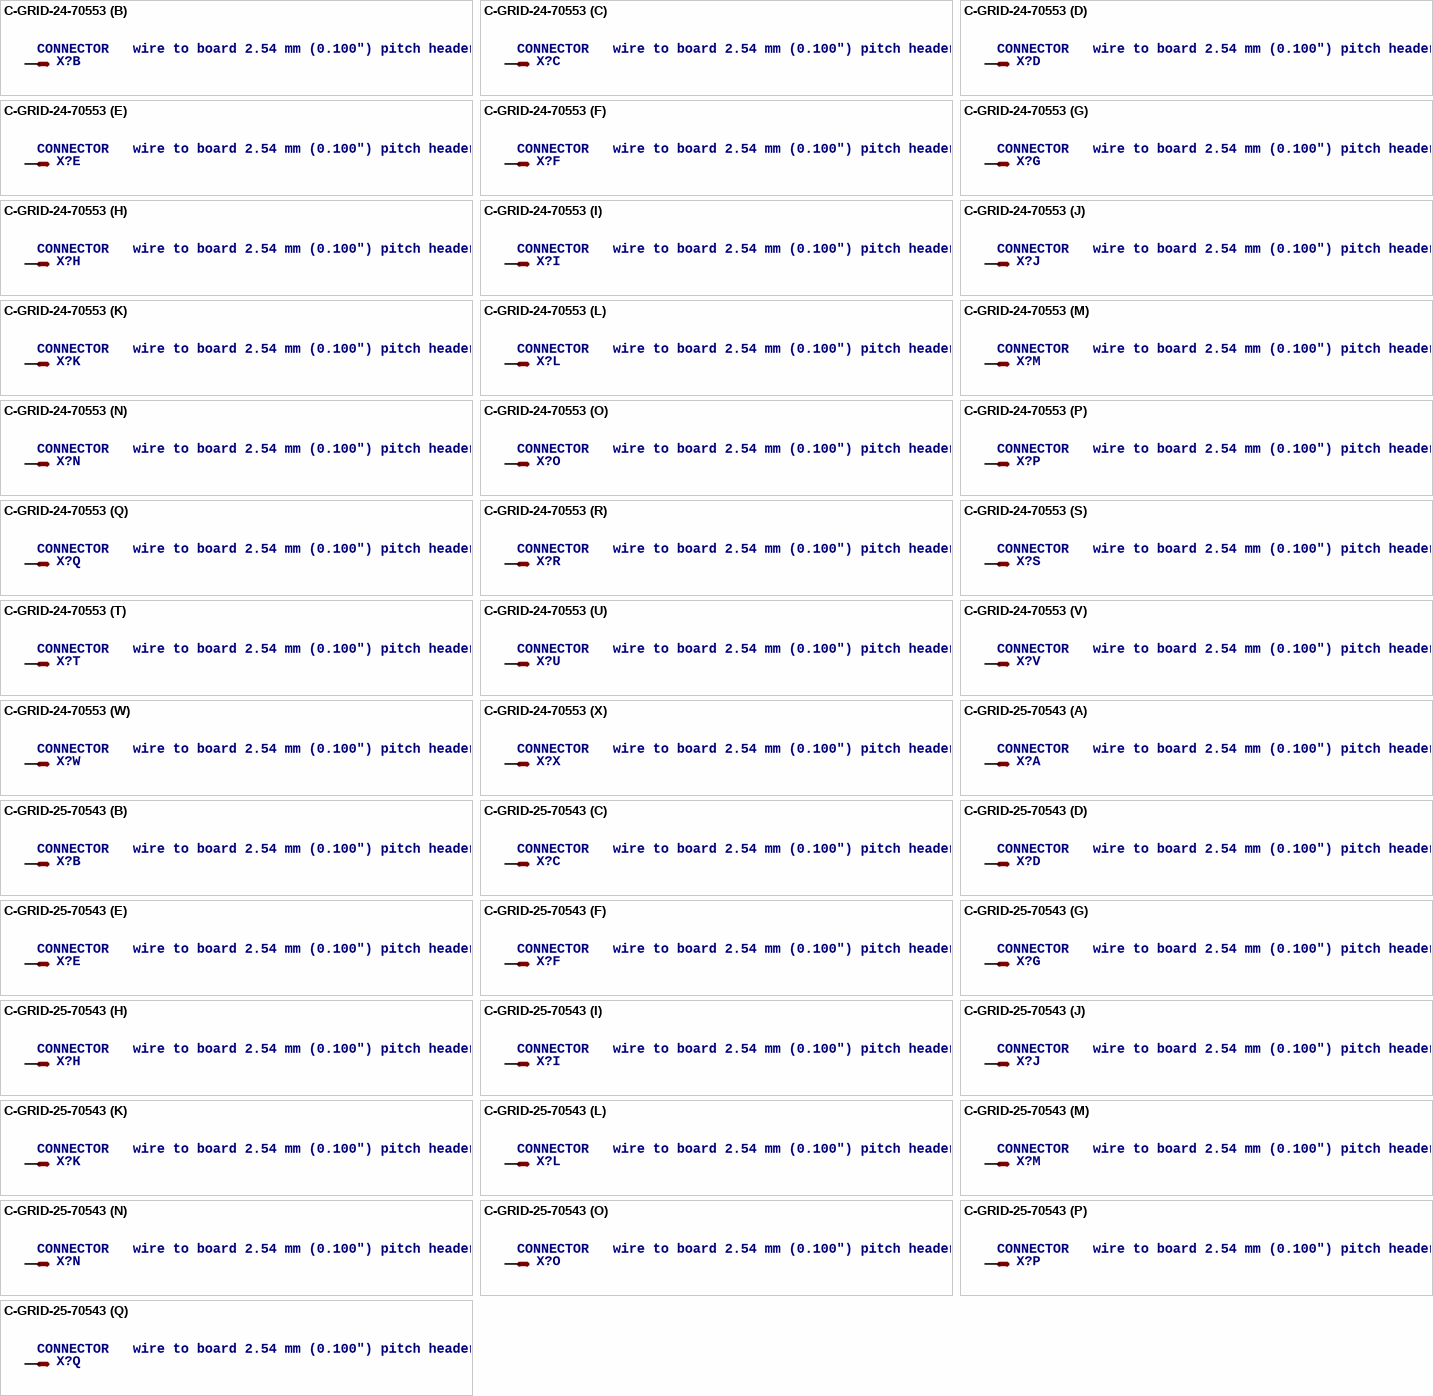
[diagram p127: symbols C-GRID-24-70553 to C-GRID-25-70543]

## C-GRID-24-70553
designator X?, comment CONNECTOR   wire to board 2.54 mm (0.100") pitch header
footprint 70553-24
part A pins: 1 S
part B pins: 2 S
part C pins: 3 S
part D pins: 4 S
part E pins: 5 S
part F pins: 6 S
part G pins: 7 S
part H pins: 8 S
part I pins: 9 S
part J pins: 10 S
part K pins: 11 S
part L pins: 12 S
part M pins: 13 S
part N pins: 14 S
part O pins: 15 S
part P pins: 16 S
part Q pins: 17 S
part R pins: 18 S
part S pins: 19 S
part T pins: 20 S
part U pins: 21 S
part V pins: 22 S
part W pins: 23 S
part X pins: 24 S

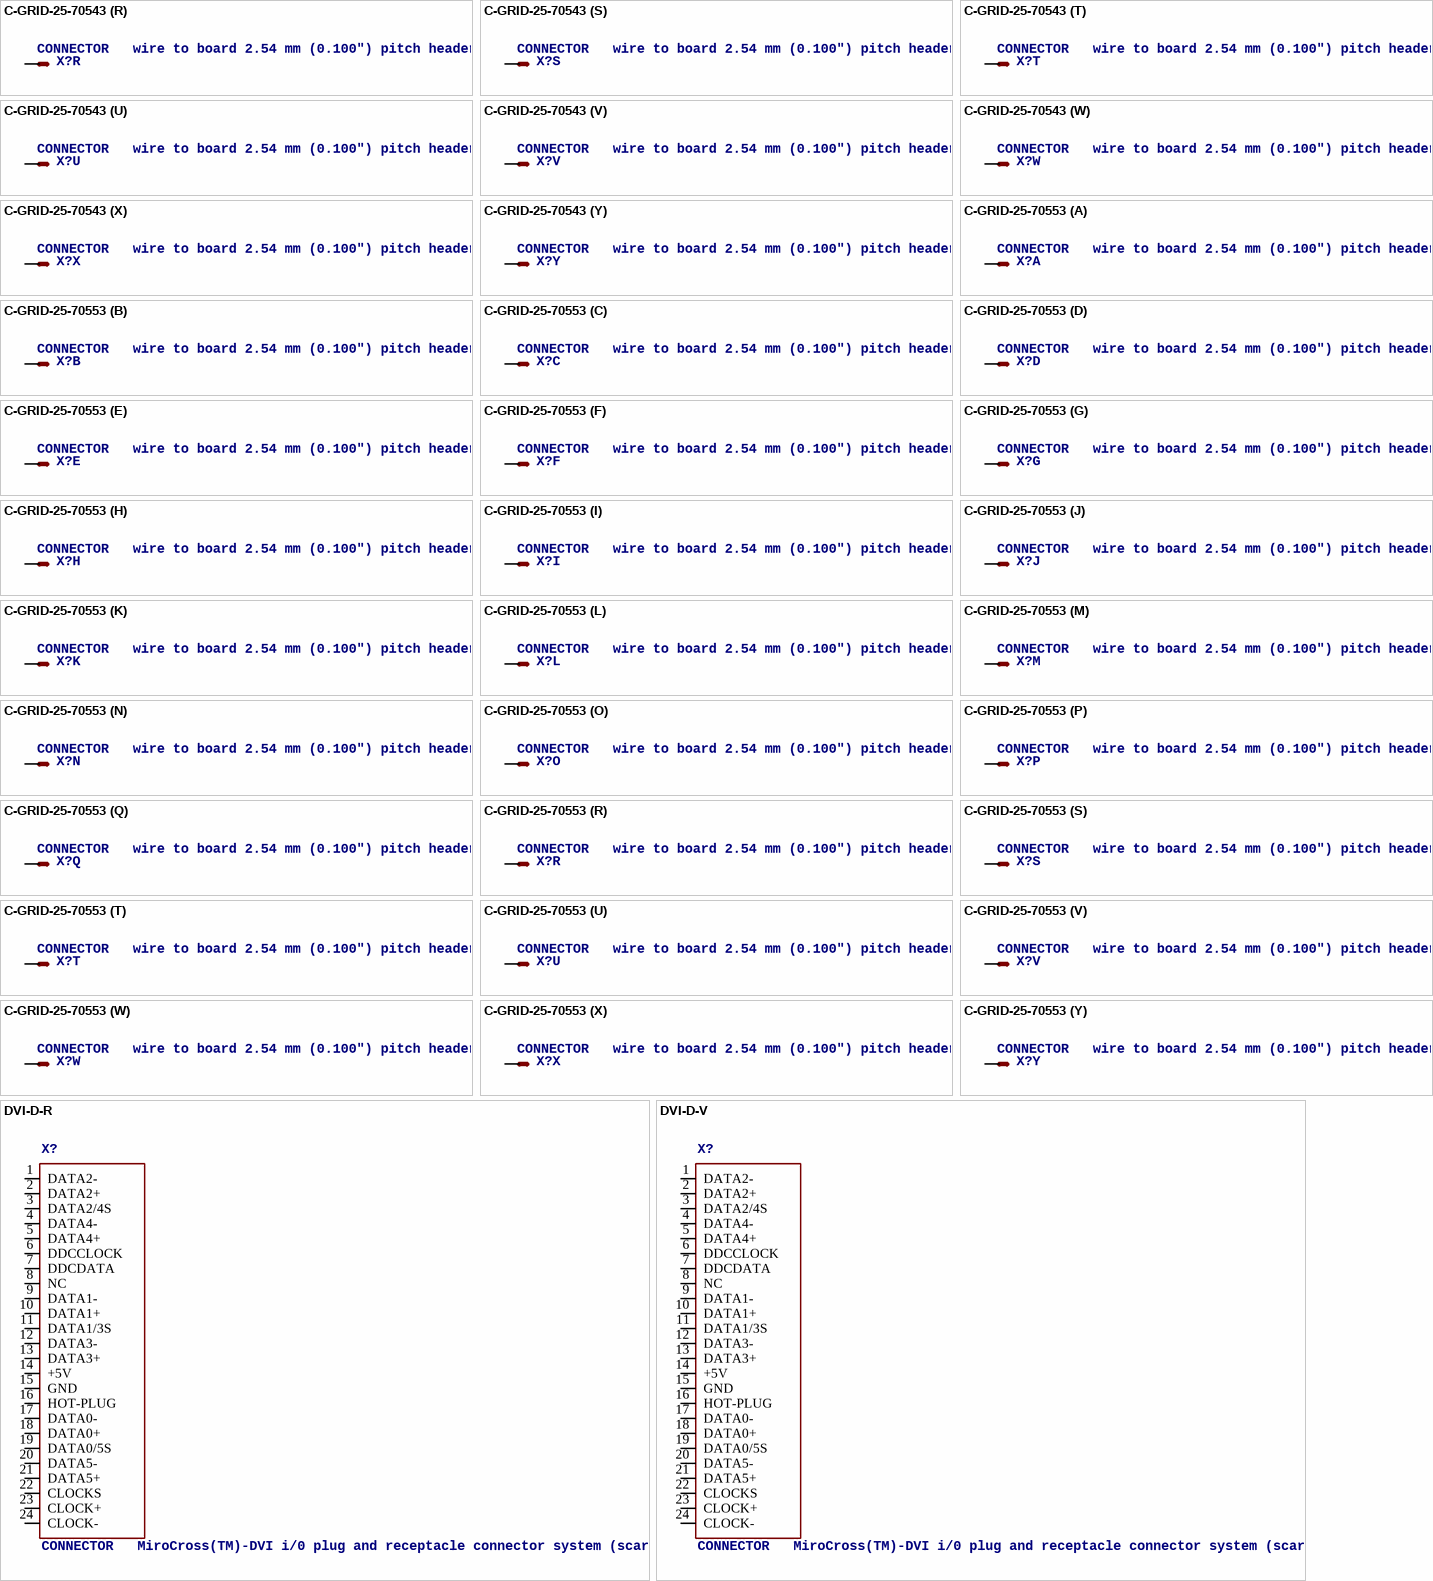
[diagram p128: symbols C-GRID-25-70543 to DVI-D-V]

## C-GRID-25-70543
designator X?, comment CONNECTOR   wire to board 2.54 mm (0.100") pitch header
footprint 70543-25
part A pins: 1 S
part B pins: 2 S
part C pins: 3 S
part D pins: 4 S
part E pins: 5 S
part F pins: 6 S
part G pins: 7 S
part H pins: 8 S
part I pins: 9 S
part J pins: 10 S
part K pins: 11 S
part L pins: 12 S
part M pins: 13 S
part N pins: 14 S
part O pins: 15 S
part P pins: 16 S
part Q pins: 17 S
part R pins: 18 S
part S pins: 19 S
part T pins: 20 S
part U pins: 21 S
part V pins: 22 S
part W pins: 23 S
part X pins: 24 S
part Y pins: 25 S

## C-GRID-25-70553
designator X?, comment CONNECTOR   wire to board 2.54 mm (0.100") pitch header
footprint 70553-25
part A pins: 1 S
part B pins: 2 S
part C pins: 3 S
part D pins: 4 S
part E pins: 5 S
part F pins: 6 S
part G pins: 7 S
part H pins: 8 S
part I pins: 9 S
part J pins: 10 S
part K pins: 11 S
part L pins: 12 S
part M pins: 13 S
part N pins: 14 S
part O pins: 15 S
part P pins: 16 S
part Q pins: 17 S
part R pins: 18 S
part S pins: 19 S
part T pins: 20 S
part U pins: 21 S
part V pins: 22 S
part W pins: 23 S
part X pins: 24 S
part Y pins: 25 S

## DVI-D-R
designator X?, comment CONNECTOR   MiroCross(TM)-DVI i/0 plug and receptacle connector system (scart)
footprint DVI-D-R
pins: 1 DATA2-, 2 DATA2+, 3 DATA2/4S, 4 DATA4-, 5 DATA4+, 6 DDCCLOCK, 7 DDCDATA, 8 NC, 9 DATA1-, 10 DATA1+, 11 DATA1/3S, 12 DATA3-, 13 DATA3+, 14 +5V (power), 15 GND (power), 16 HOT-PLUG, 17 DATA0-, 18 DATA0+, 19 DATA0/5S, 20 DATA5-, 21 DATA5+, 22 CLOCKS, 23 CLOCK+, 24 CLOCK-

## DVI-D-V
designator X?, comment CONNECTOR   MiroCross(TM)-DVI i/0 plug and receptacle connector system (scart)
footprint DVI-D-V
pins: 1 DATA2-, 2 DATA2+, 3 DATA2/4S, 4 DATA4-, 5 DATA4+, 6 DDCCLOCK, 7 DDCDATA, 8 NC, 9 DATA1-, 10 DATA1+, 11 DATA1/3S, 12 DATA3-, 13 DATA3+, 14 +5V (power), 15 GND (power), 16 HOT-PLUG, 17 DATA0-, 18 DATA0+, 19 DATA0/5S, 20 DATA5-, 21 DATA5+, 22 CLOCKS, 23 CLOCK+, 24 CLOCK-

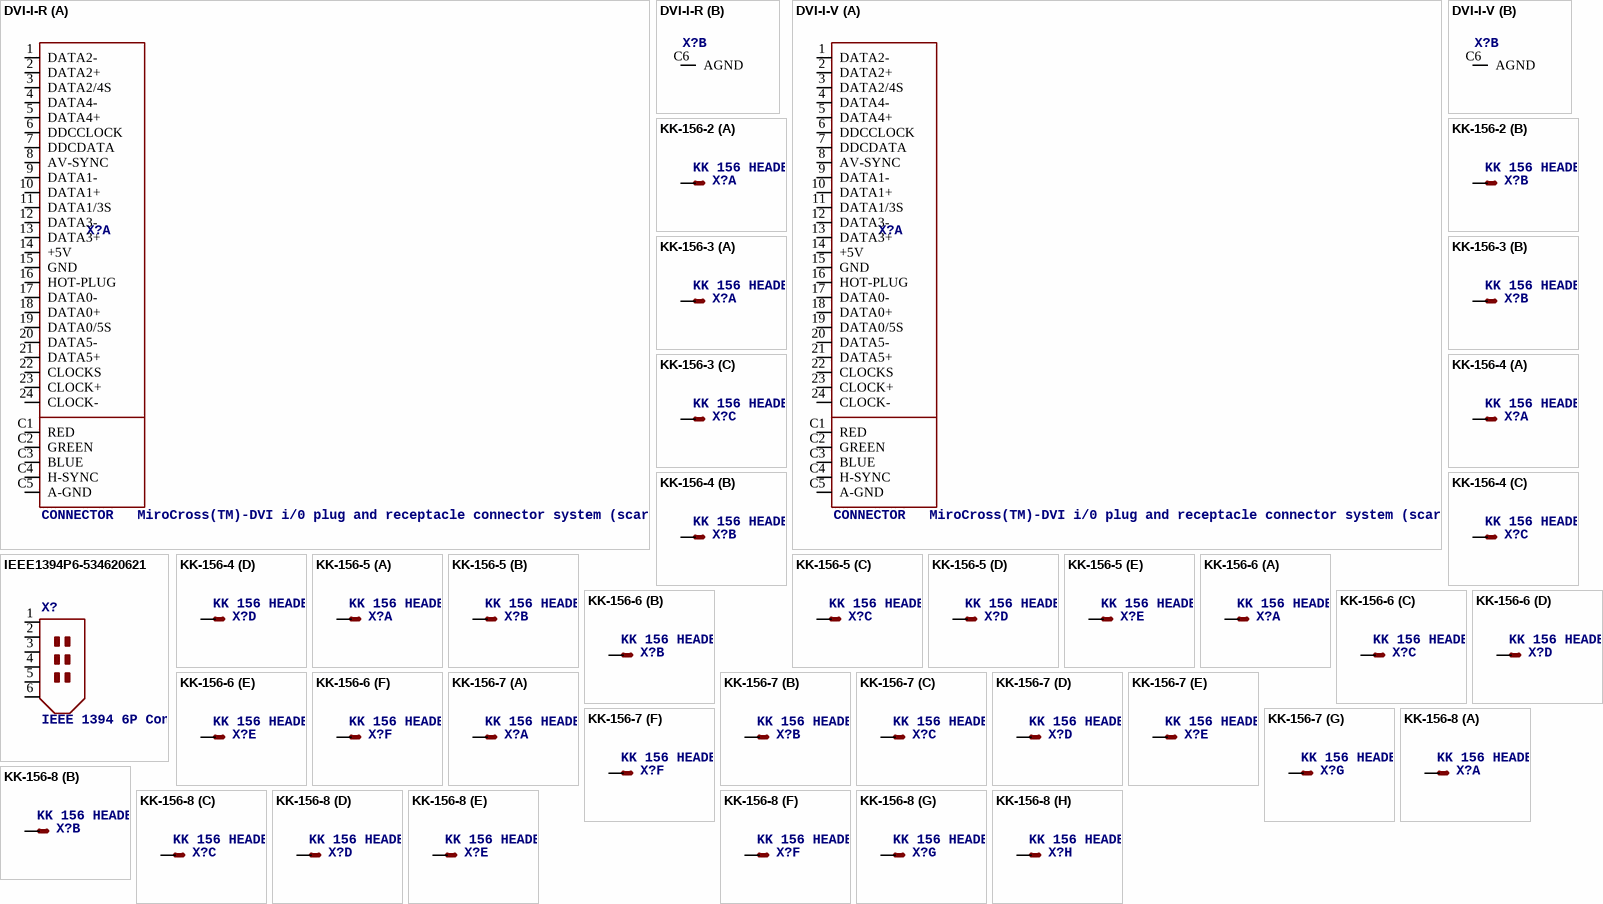
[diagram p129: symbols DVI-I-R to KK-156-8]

## DVI-I-R
designator X?, comment CONNECTOR   MiroCross(TM)-DVI i/0 plug and receptacle connector system (scart)
footprint DVI-I-R
part A pins: 1 DATA2-, 2 DATA2+, 3 DATA2/4S, 4 DATA4-, 5 DATA4+, 6 DDCCLOCK, 7 DDCDATA, 8 AV-SYNC, 9 DATA1-, 10 DATA1+, 11 DATA1/3S, 12 DATA3-, 13 DATA3+, 14 +5V (power), 15 GND (power), 16 HOT-PLUG, 17 DATA0-, 18 DATA0+, 19 DATA0/5S, 20 DATA5-, 21 DATA5+, 22 CLOCKS, 23 CLOCK+, 24 CLOCK-, C1 RED, C2 GREEN, C3 BLUE, C4 H-SYNC, C5 A-GND (power)
part B pins: C6 AGND (power)

## DVI-I-V
designator X?, comment CONNECTOR   MiroCross(TM)-DVI i/0 plug and receptacle connector system (scart)
footprint DVI-I-V
part A pins: 1 DATA2-, 2 DATA2+, 3 DATA2/4S, 4 DATA4-, 5 DATA4+, 6 DDCCLOCK, 7 DDCDATA, 8 AV-SYNC, 9 DATA1-, 10 DATA1+, 11 DATA1/3S, 12 DATA3-, 13 DATA3+, 14 +5V (power), 15 GND (power), 16 HOT-PLUG, 17 DATA0-, 18 DATA0+, 19 DATA0/5S, 20 DATA5-, 21 DATA5+, 22 CLOCKS, 23 CLOCK+, 24 CLOCK-, C1 RED, C2 GREEN, C3 BLUE, C4 H-SYNC, C5 A-GND (power)
part B pins: C6 AGND (power)

## IEEE1394P6-534620621
designator X?, comment IEEE 1394 6P Connector   Source: http://www.molex.com/pdm_docs/sd/534620621_sd.pdf
footprint 534620621_SD
pins: 1, 2, 3, 4, 5, 6

## KK-156-2
designator X?, comment KK 156 HEADER   Source: http://www.molex.com/pdm_docs/sd/026604100_sd.pdf
footprint KK-156-2
part A pins: 1 S
part B pins: 2 S

## KK-156-3
designator X?, comment KK 156 HEADER   Source: http://www.molex.com/pdm_docs/sd/026604100_sd.pdf
footprint KK-156-3
part A pins: 1 S
part B pins: 2 S
part C pins: 3 S

## KK-156-4
designator X?, comment KK 156 HEADER   Source: http://www.molex.com/pdm_docs/sd/026604100_sd.pdf
footprint KK-156-4
part A pins: 1 S
part B pins: 2 S
part C pins: 3 S
part D pins: 4 S

## KK-156-5
designator X?, comment KK 156 HEADER   Source: http://www.molex.com/pdm_docs/sd/026604100_sd.pdf
footprint KK-156-5
part A pins: 1 S
part B pins: 2 S
part C pins: 3 S
part D pins: 4 S
part E pins: 5 S

## KK-156-6
designator X?, comment KK 156 HEADER   Source: http://www.molex.com/pdm_docs/sd/026604100_sd.pdf
footprint KK-156-6
part A pins: 1 S
part B pins: 2 S
part C pins: 3 S
part D pins: 4 S
part E pins: 5 S
part F pins: 6 S

## KK-156-7
designator X?, comment KK 156 HEADER   Source: http://www.molex.com/pdm_docs/sd/026604100_sd.pdf
footprint KK-156-7
part A pins: 1 S
part B pins: 2 S
part C pins: 3 S
part D pins: 4 S
part E pins: 5 S
part F pins: 6 S
part G pins: 7 S

## KK-156-8
designator X?, comment KK 156 HEADER   Source: http://www.molex.com/pdm_docs/sd/026604100_sd.pdf
footprint KK-156-8
part A pins: 1 S
part B pins: 2 S
part C pins: 3 S
part D pins: 4 S
part E pins: 5 S
part F pins: 6 S
part G pins: 7 S
part H pins: 8 S

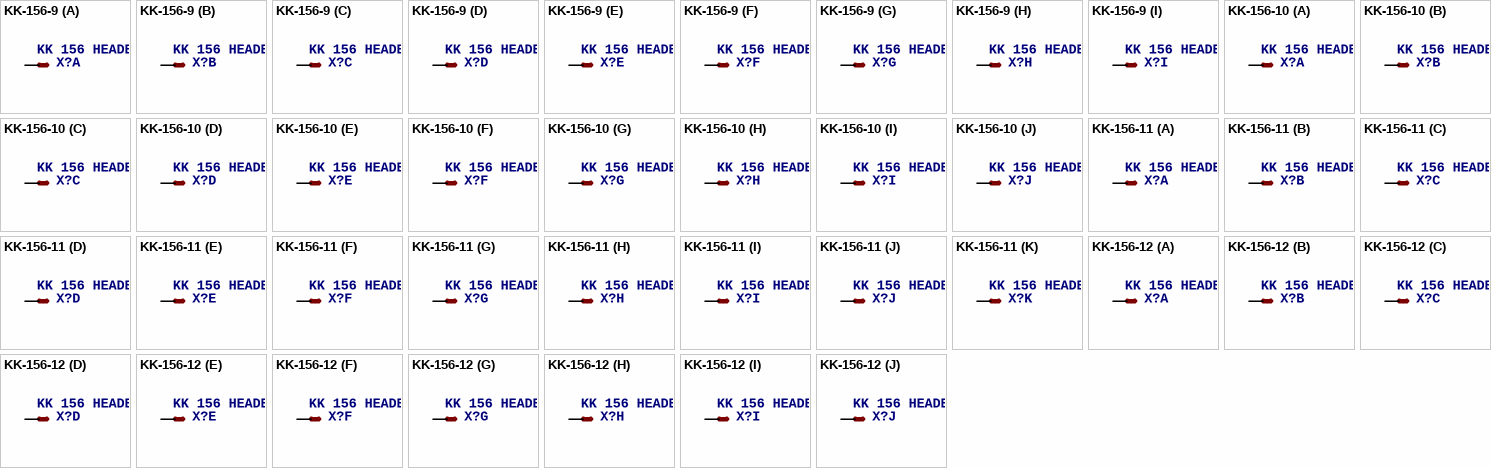
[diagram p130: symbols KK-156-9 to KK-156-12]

## KK-156-9
designator X?, comment KK 156 HEADER   Source: http://www.molex.com/pdm_docs/sd/026604100_sd.pdf
footprint KK-156-9
part A pins: 1 S
part B pins: 2 S
part C pins: 3 S
part D pins: 4 S
part E pins: 5 S
part F pins: 6 S
part G pins: 7 S
part H pins: 8 S
part I pins: 9 S

## KK-156-10
designator X?, comment KK 156 HEADER   Source: http://www.molex.com/pdm_docs/sd/026604100_sd.pdf
footprint KK-156-10
part A pins: 1 S
part B pins: 2 S
part C pins: 3 S
part D pins: 4 S
part E pins: 5 S
part F pins: 6 S
part G pins: 7 S
part H pins: 8 S
part I pins: 9 S
part J pins: 10 S

## KK-156-11
designator X?, comment KK 156 HEADER   Source: http://www.molex.com/pdm_docs/sd/026604100_sd.pdf
footprint KK-156-11
part A pins: 1 S
part B pins: 2 S
part C pins: 3 S
part D pins: 4 S
part E pins: 5 S
part F pins: 6 S
part G pins: 7 S
part H pins: 8 S
part I pins: 9 S
part J pins: 10 S
part K pins: 11 S

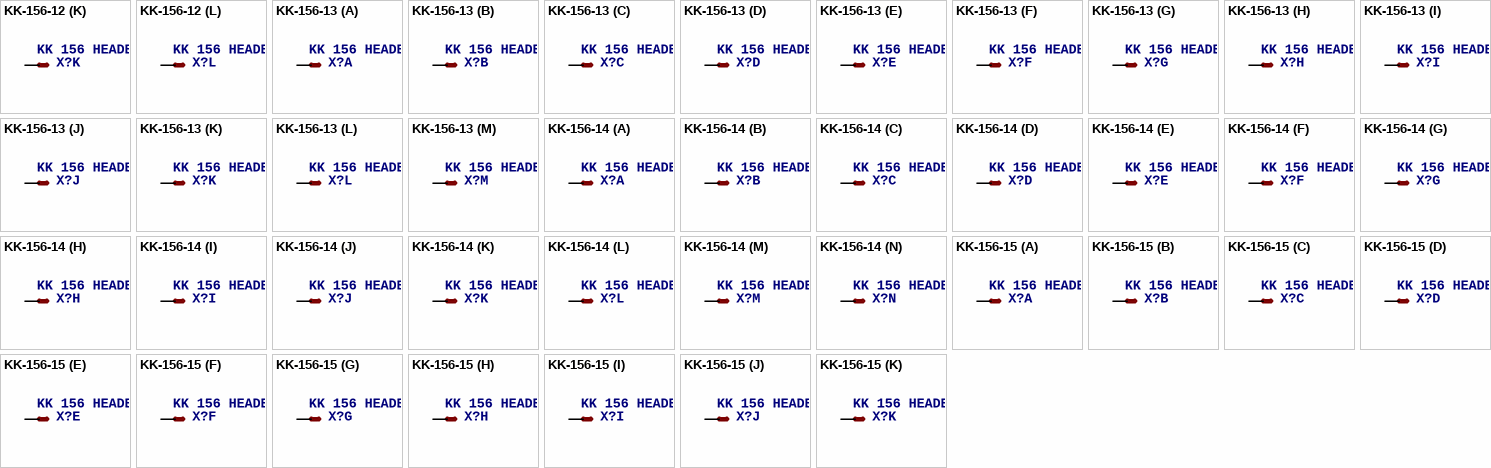
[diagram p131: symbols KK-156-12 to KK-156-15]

## KK-156-12
designator X?, comment KK 156 HEADER   Source: http://www.molex.com/pdm_docs/sd/026604100_sd.pdf
footprint KK-156-12
part A pins: 1 S
part B pins: 2 S
part C pins: 3 S
part D pins: 4 S
part E pins: 5 S
part F pins: 6 S
part G pins: 7 S
part H pins: 8 S
part I pins: 9 S
part J pins: 10 S
part K pins: 11 S
part L pins: 12 S

## KK-156-13
designator X?, comment KK 156 HEADER   Source: http://www.molex.com/pdm_docs/sd/026604100_sd.pdf
footprint KK-156-13
part A pins: 1 S
part B pins: 2 S
part C pins: 3 S
part D pins: 4 S
part E pins: 5 S
part F pins: 6 S
part G pins: 7 S
part H pins: 8 S
part I pins: 9 S
part J pins: 10 S
part K pins: 11 S
part L pins: 12 S
part M pins: 13 S

## KK-156-14
designator X?, comment KK 156 HEADER   Source: http://www.molex.com/pdm_docs/sd/026604100_sd.pdf
footprint KK-156-14
part A pins: 1 S
part B pins: 2 S
part C pins: 3 S
part D pins: 4 S
part E pins: 5 S
part F pins: 6 S
part G pins: 7 S
part H pins: 8 S
part I pins: 9 S
part J pins: 10 S
part K pins: 11 S
part L pins: 12 S
part M pins: 13 S
part N pins: 14 S

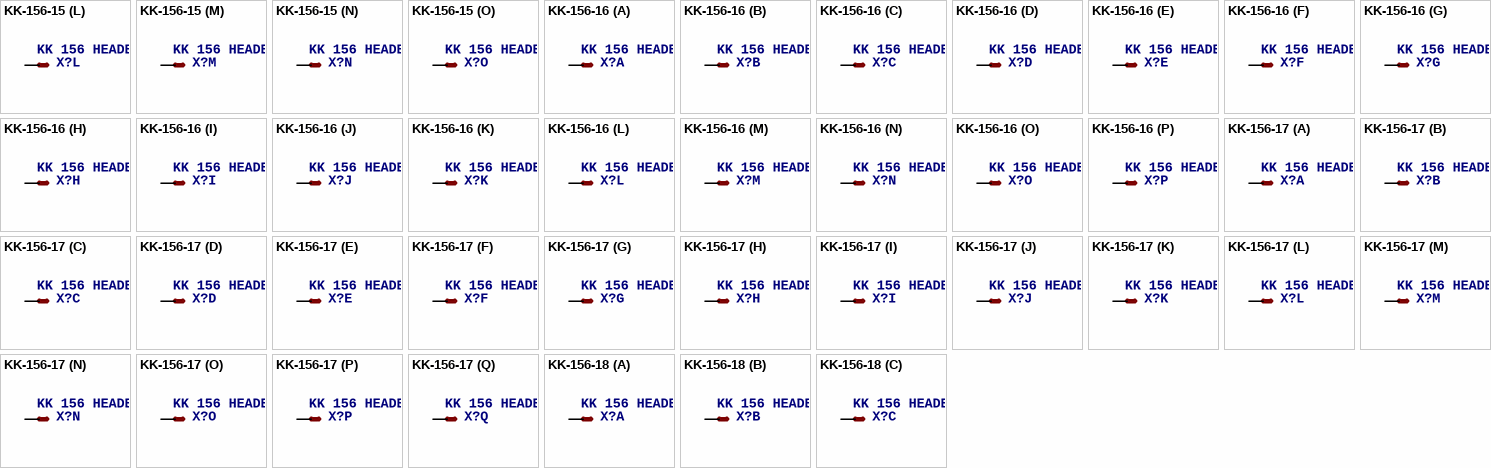
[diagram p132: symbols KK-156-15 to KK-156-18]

## KK-156-15
designator X?, comment KK 156 HEADER   Source: http://www.molex.com/pdm_docs/sd/026604100_sd.pdf
footprint KK-156-15
part A pins: 1 S
part B pins: 2 S
part C pins: 3 S
part D pins: 4 S
part E pins: 5 S
part F pins: 6 S
part G pins: 7 S
part H pins: 8 S
part I pins: 9 S
part J pins: 10 S
part K pins: 11 S
part L pins: 12 S
part M pins: 13 S
part N pins: 14 S
part O pins: 15 S

## KK-156-16
designator X?, comment KK 156 HEADER   Source: http://www.molex.com/pdm_docs/sd/026604100_sd.pdf
footprint KK-156-16
part A pins: 1 S
part B pins: 2 S
part C pins: 3 S
part D pins: 4 S
part E pins: 5 S
part F pins: 6 S
part G pins: 7 S
part H pins: 8 S
part I pins: 9 S
part J pins: 10 S
part K pins: 11 S
part L pins: 12 S
part M pins: 13 S
part N pins: 14 S
part O pins: 15 S
part P pins: 16 S

## KK-156-17
designator X?, comment KK 156 HEADER   Source: http://www.molex.com/pdm_docs/sd/026604100_sd.pdf
footprint KK-156-17
part A pins: 1 S
part B pins: 2 S
part C pins: 3 S
part D pins: 4 S
part E pins: 5 S
part F pins: 6 S
part G pins: 7 S
part H pins: 8 S
part I pins: 9 S
part J pins: 10 S
part K pins: 11 S
part L pins: 12 S
part M pins: 13 S
part N pins: 14 S
part O pins: 15 S
part P pins: 16 S
part Q pins: 17 S

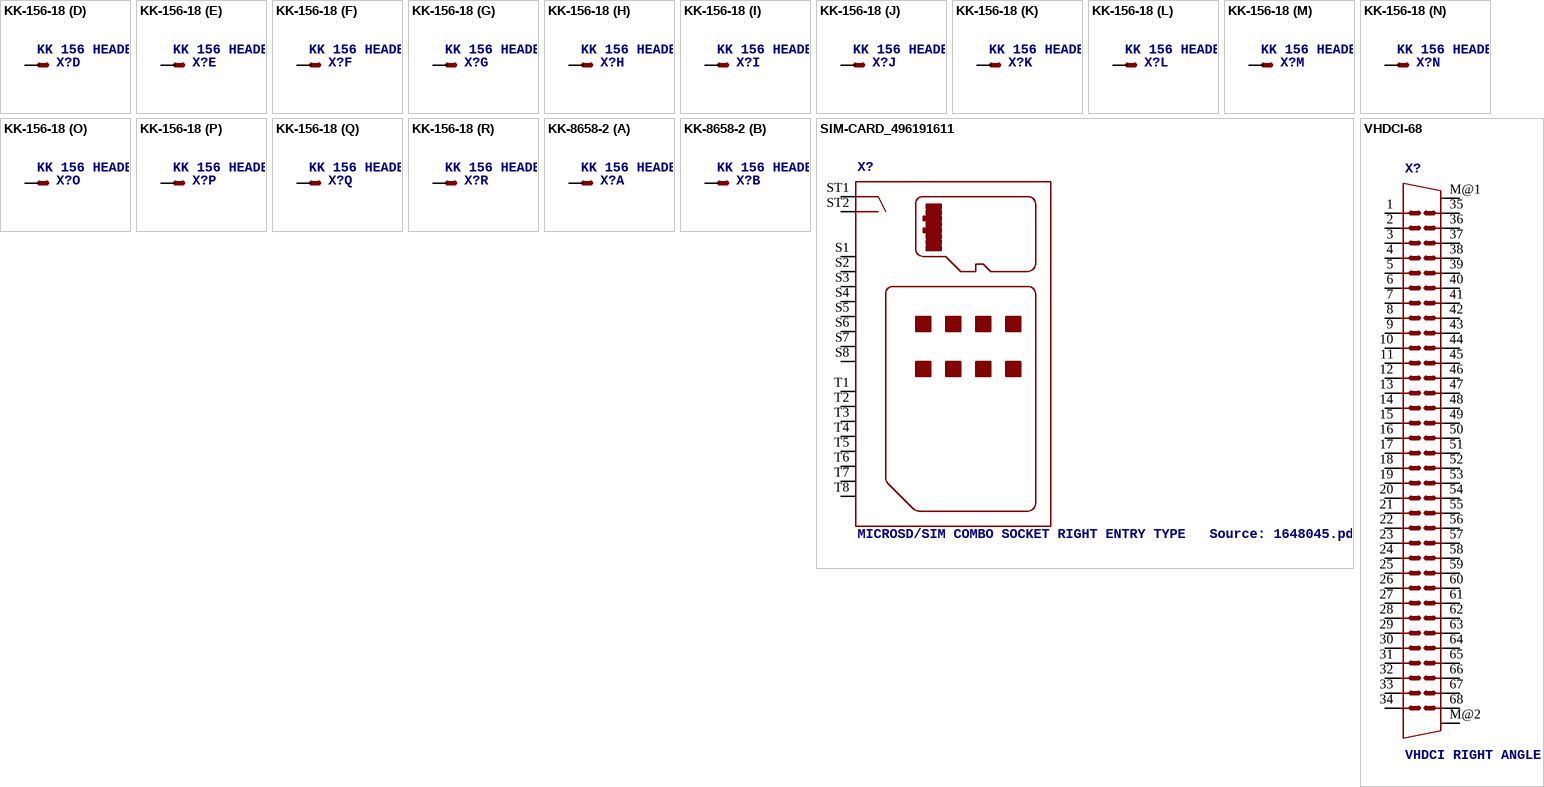
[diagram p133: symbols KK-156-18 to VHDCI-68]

## KK-156-18
designator X?, comment KK 156 HEADER   Source: http://www.molex.com/pdm_docs/sd/026604100_sd.pdf
footprint KK-156-18
part A pins: 1 S
part B pins: 2 S
part C pins: 3 S
part D pins: 4 S
part E pins: 5 S
part F pins: 6 S
part G pins: 7 S
part H pins: 8 S
part I pins: 9 S
part J pins: 10 S
part K pins: 11 S
part L pins: 12 S
part M pins: 13 S
part N pins: 14 S
part O pins: 15 S
part P pins: 16 S
part Q pins: 17 S
part R pins: 18 S

## KK-8658-2
designator X?, comment KK 156 HEADER   Source: http://www.molex.com/pdm_docs/sd/026604100_sd.pdf
footprint KK-8658-2
part A pins: 1 S
part B pins: 2 S

## SIM-CARD_496191611
designator X?, comment MICROSD/SIM COMBO SOCKET RIGHT ENTRY TYPE   Source: 1648045.pdf
footprint SIM-CARD_496191611
pins: S1, S2, S3, S4, S5, S6, S7, S8, ST1, ST2, T1, T2, T3, T4, T5, T6, T7, T8

## VHDCI-68
designator X?, comment VHDCI RIGHT ANGLE ASSEMBLY 68-Pin 73412-0110   86-Pin-VHDCI-Anschluss (rechtwinklig) Source:  Data sheet
footprint VHDCI-68
pins: 1, 2, 3, 4, 5, 6, 7, 8, 9, 10, 11, 12, 13, 14, 15, 16, 17, 18, 19, 20, 21, 22, 23, 24, 25, 26, 27, 28, 29, 30, 31, 32, 33, 34, 35, 36, 37, 38, 39, 40, 41, 42, 43, 44, 45, 46, 47, 48, 49, 50, 51, 52, 53, 54, 55, 56, 57, 58, 59, 60, 61, 62, 63, 64, 65, 66, 67, 68, M@1 S@1, M@2 S@2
